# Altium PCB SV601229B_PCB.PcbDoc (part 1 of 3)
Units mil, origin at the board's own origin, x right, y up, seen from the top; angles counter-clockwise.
Board outline 3875 x 2375 mil, 10 copper layers (Top Layer, MidLayer1, MidLayer2, MidLayer3, MidLayer4, MidLayer5, MidLayer6, MidLayer7, MidLayer8, Bottom Layer), stack 98 mil thick; 184 components, 75 nets, 694 pads, 496 vias.
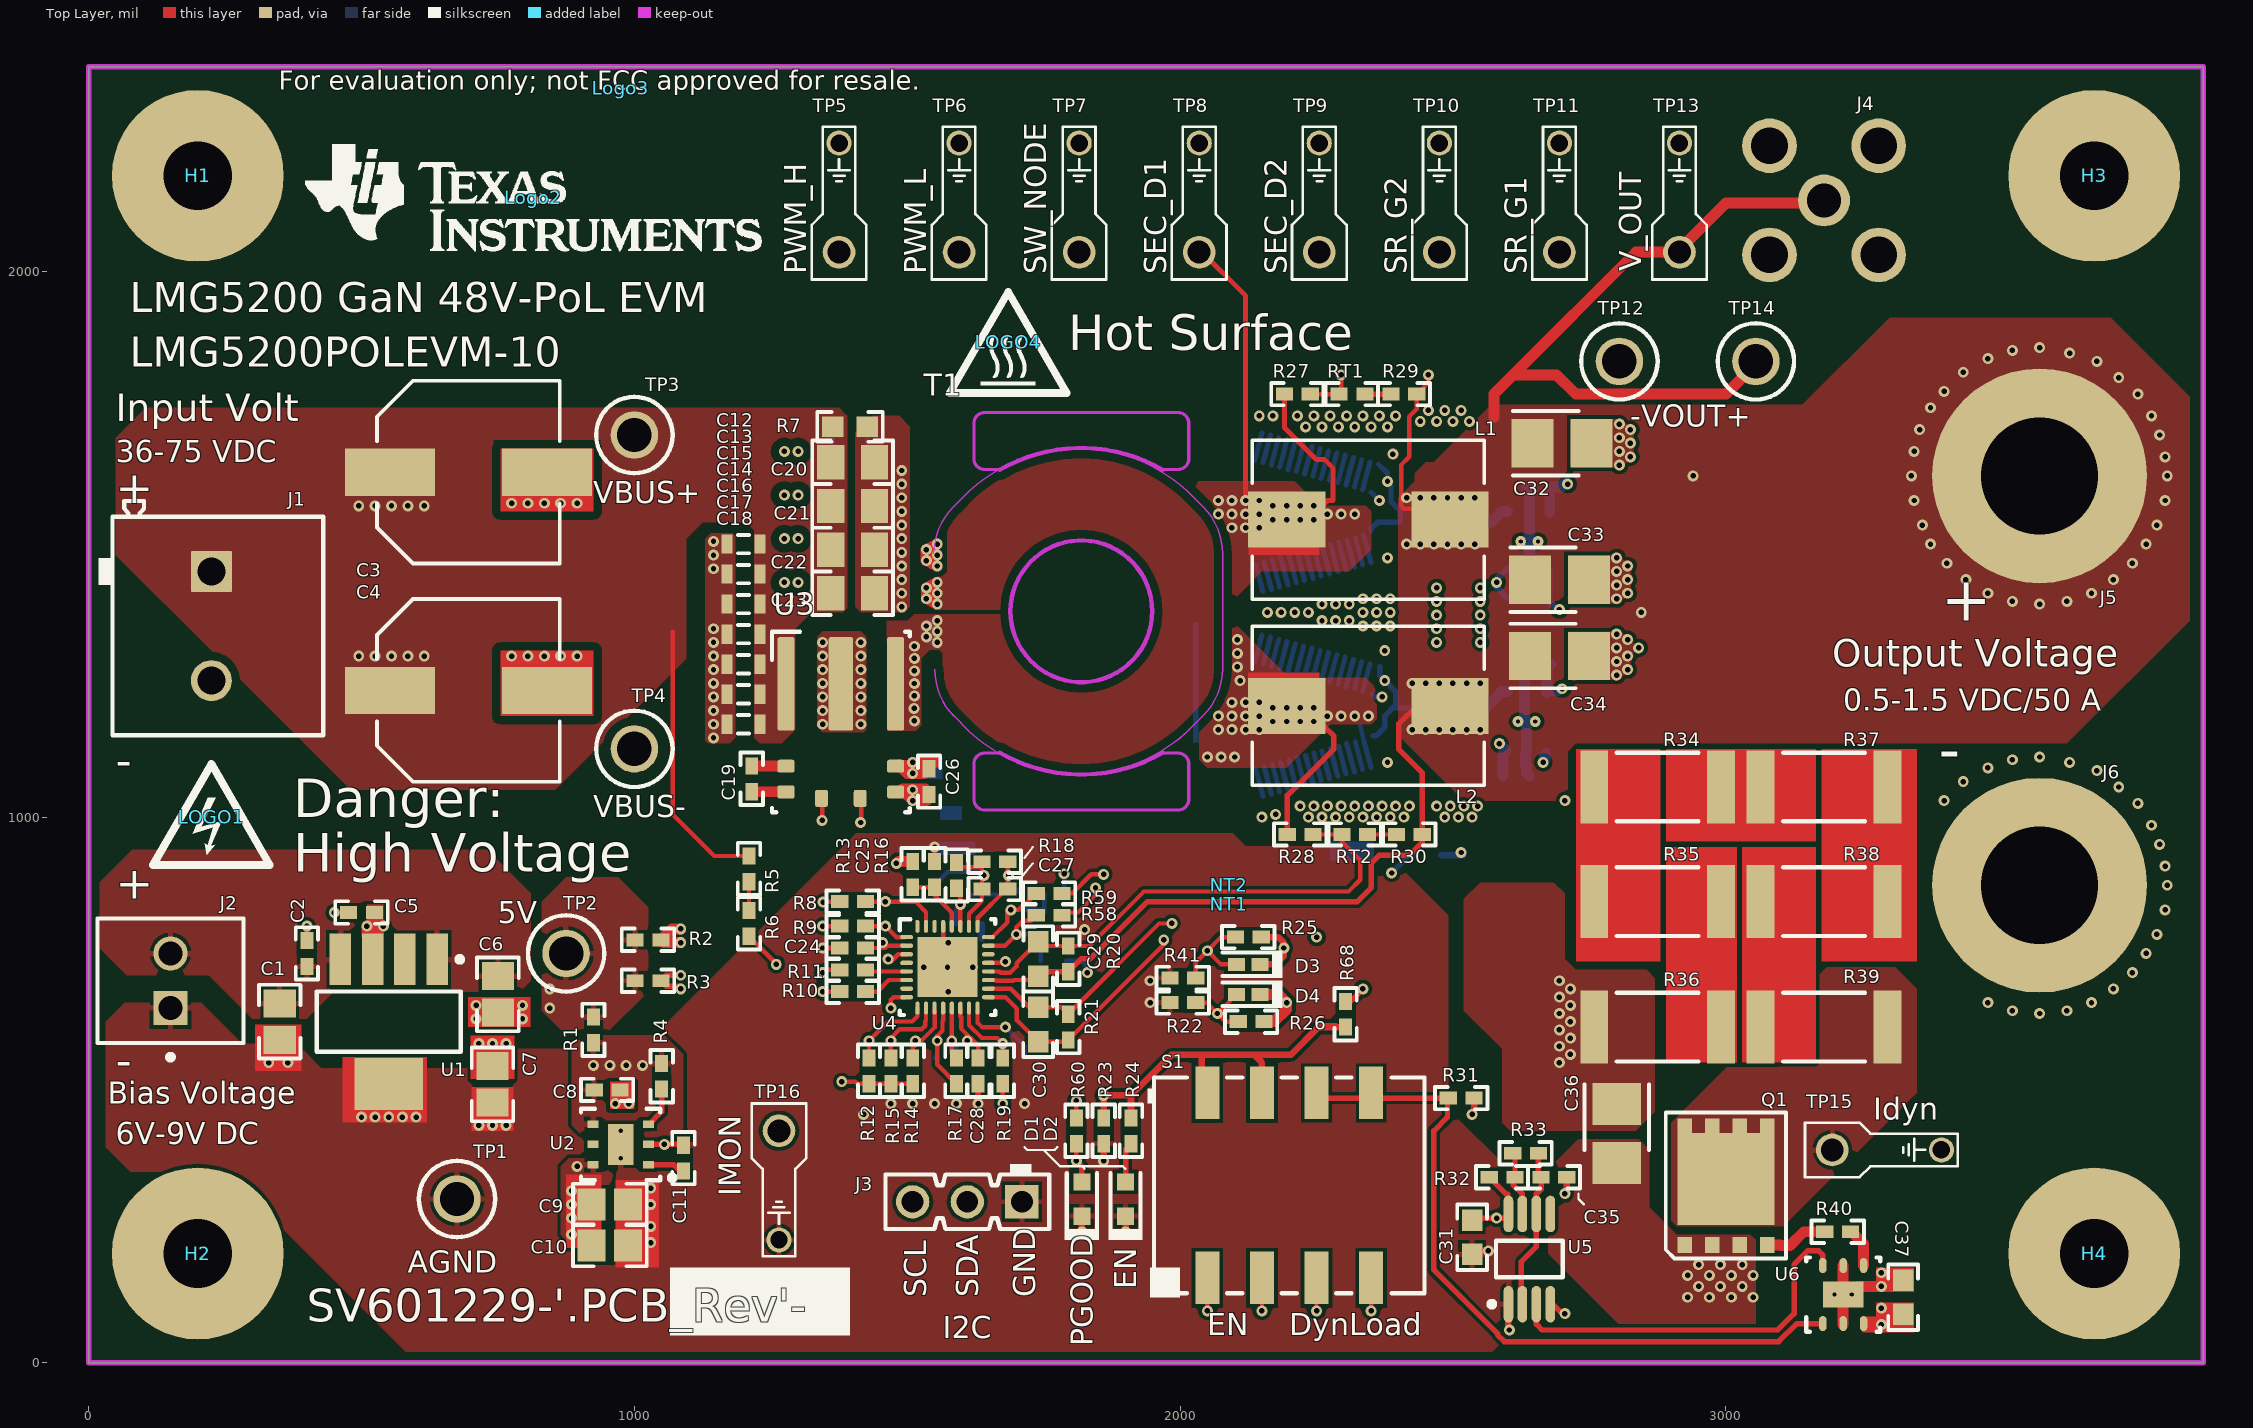
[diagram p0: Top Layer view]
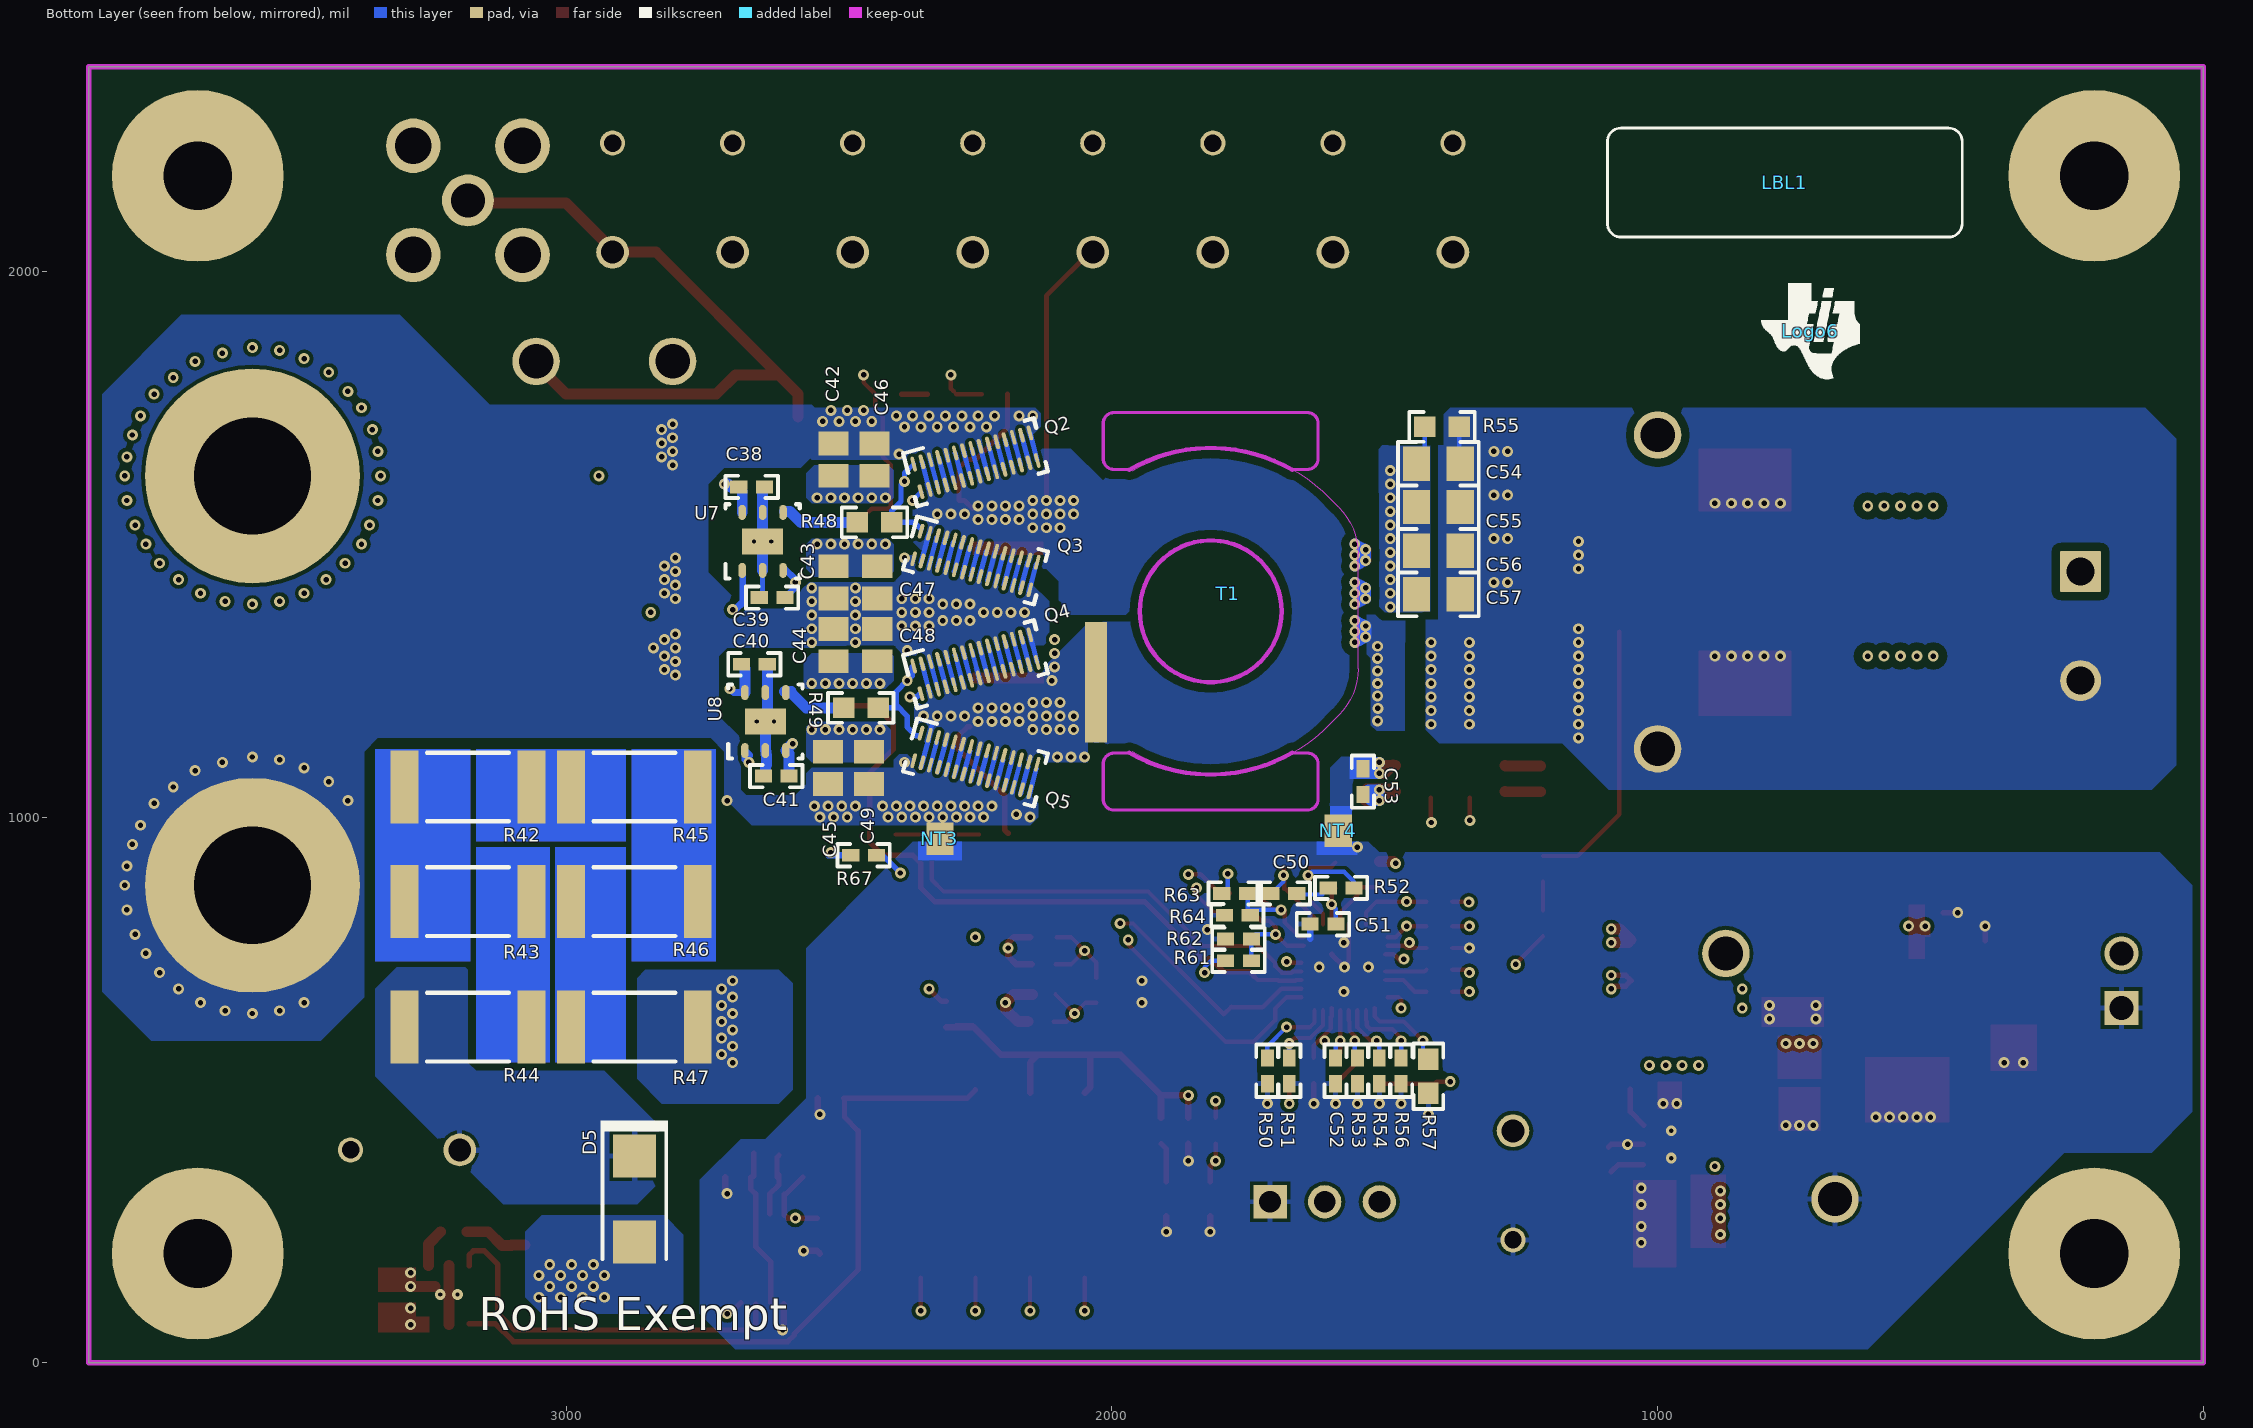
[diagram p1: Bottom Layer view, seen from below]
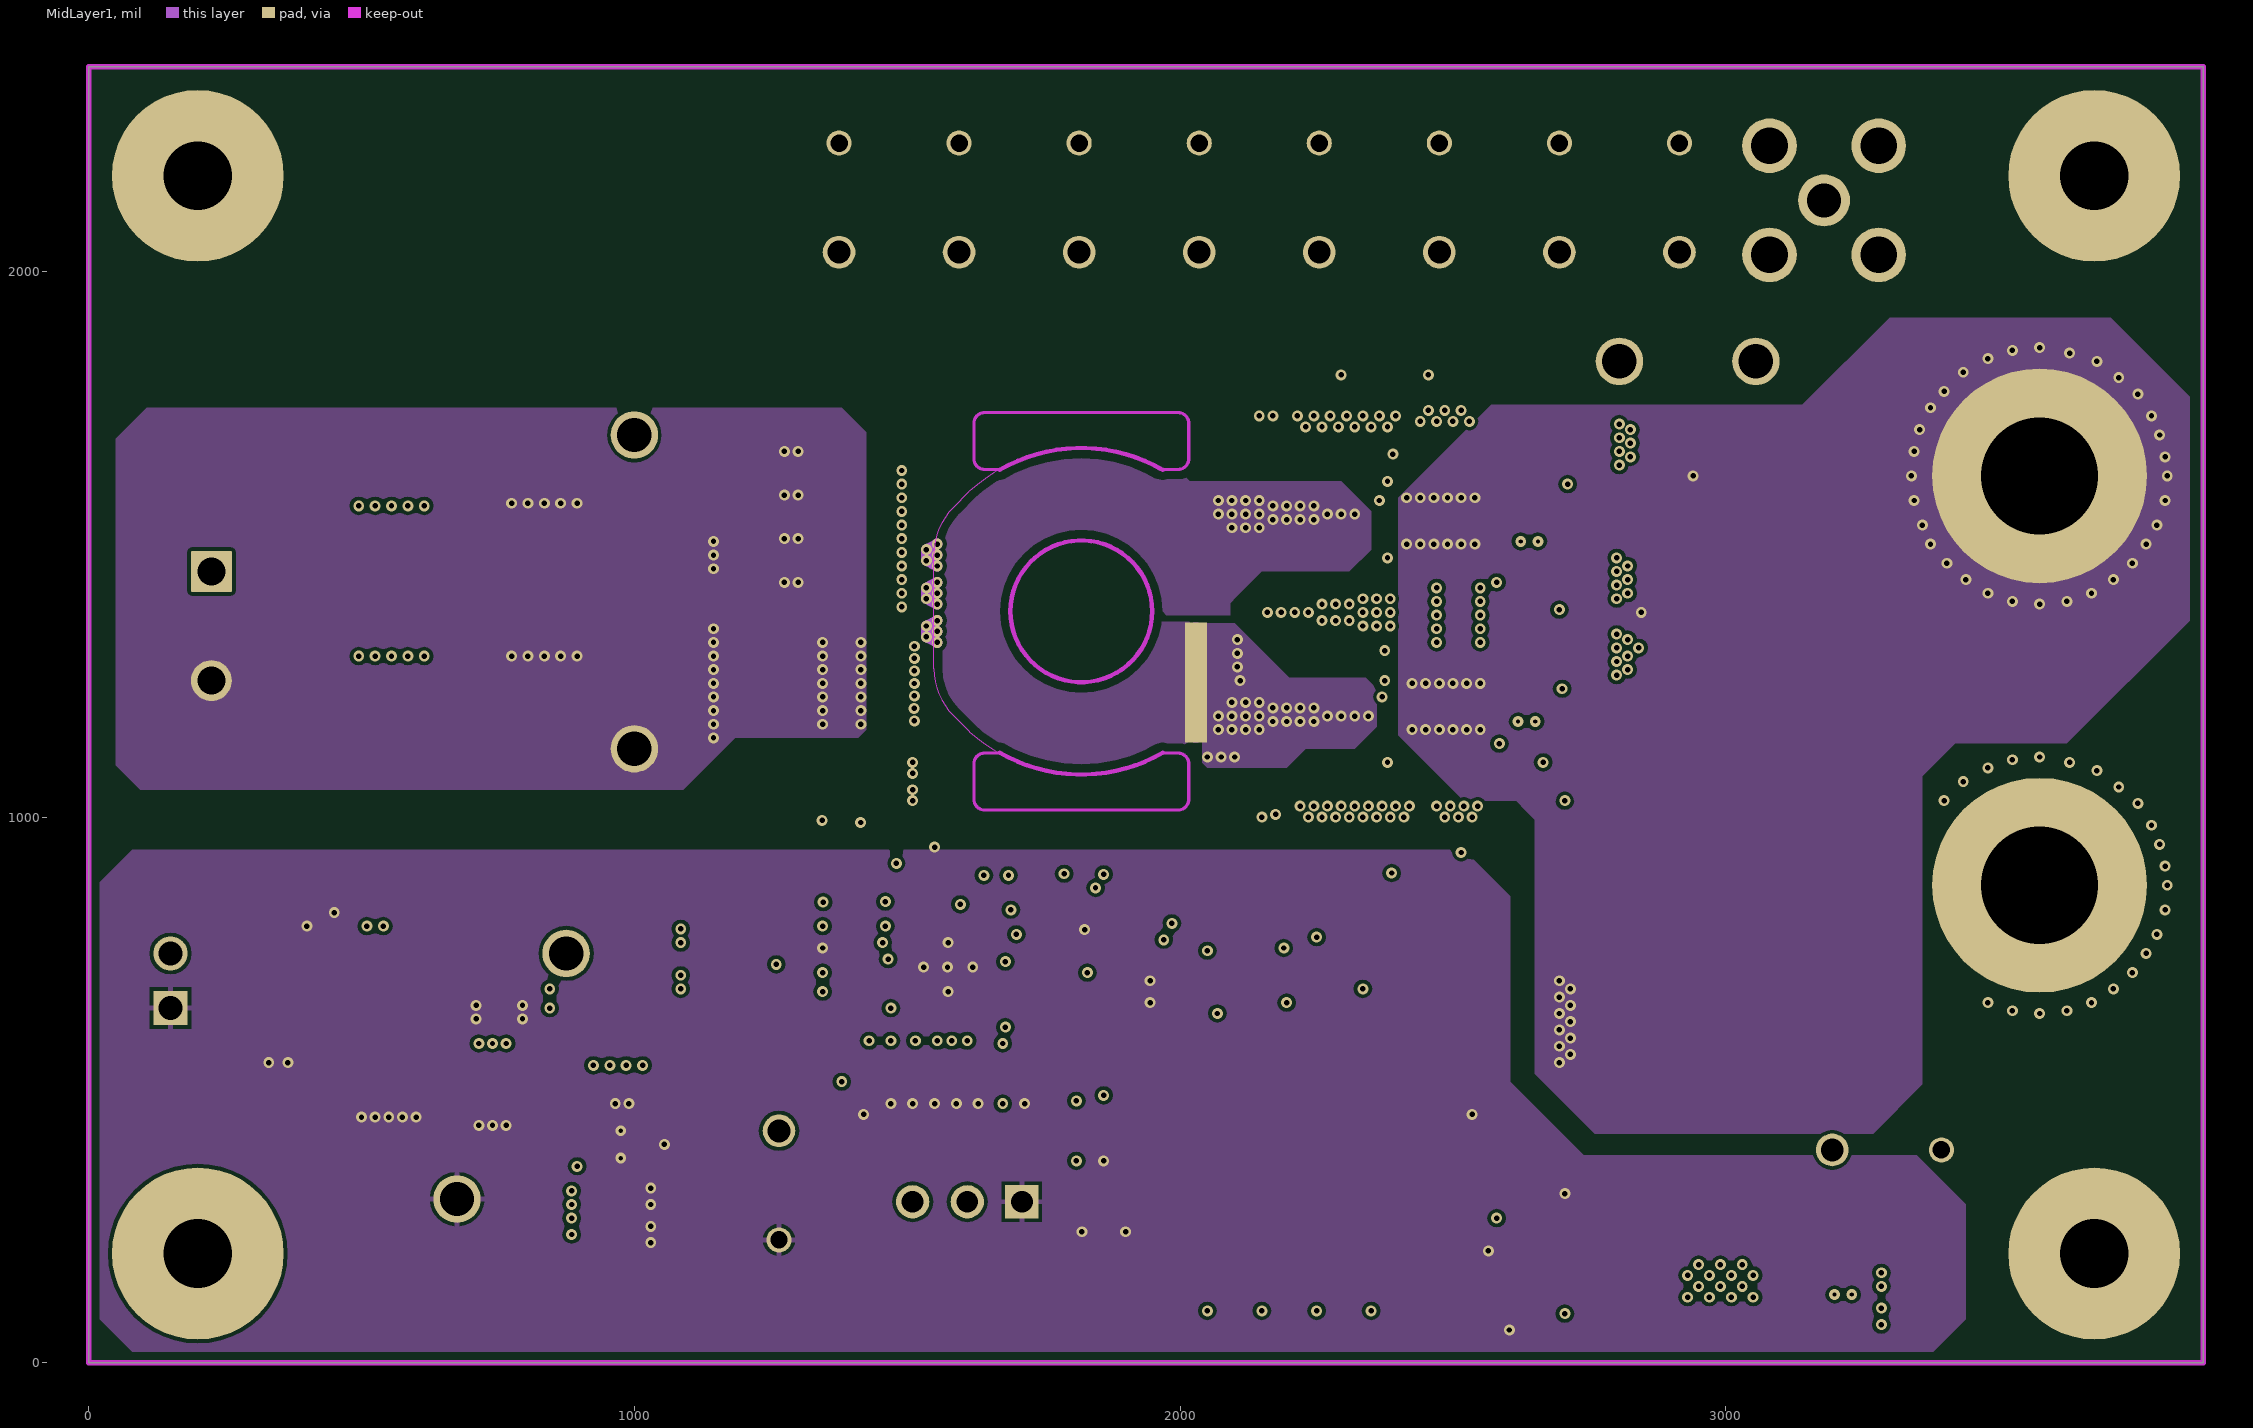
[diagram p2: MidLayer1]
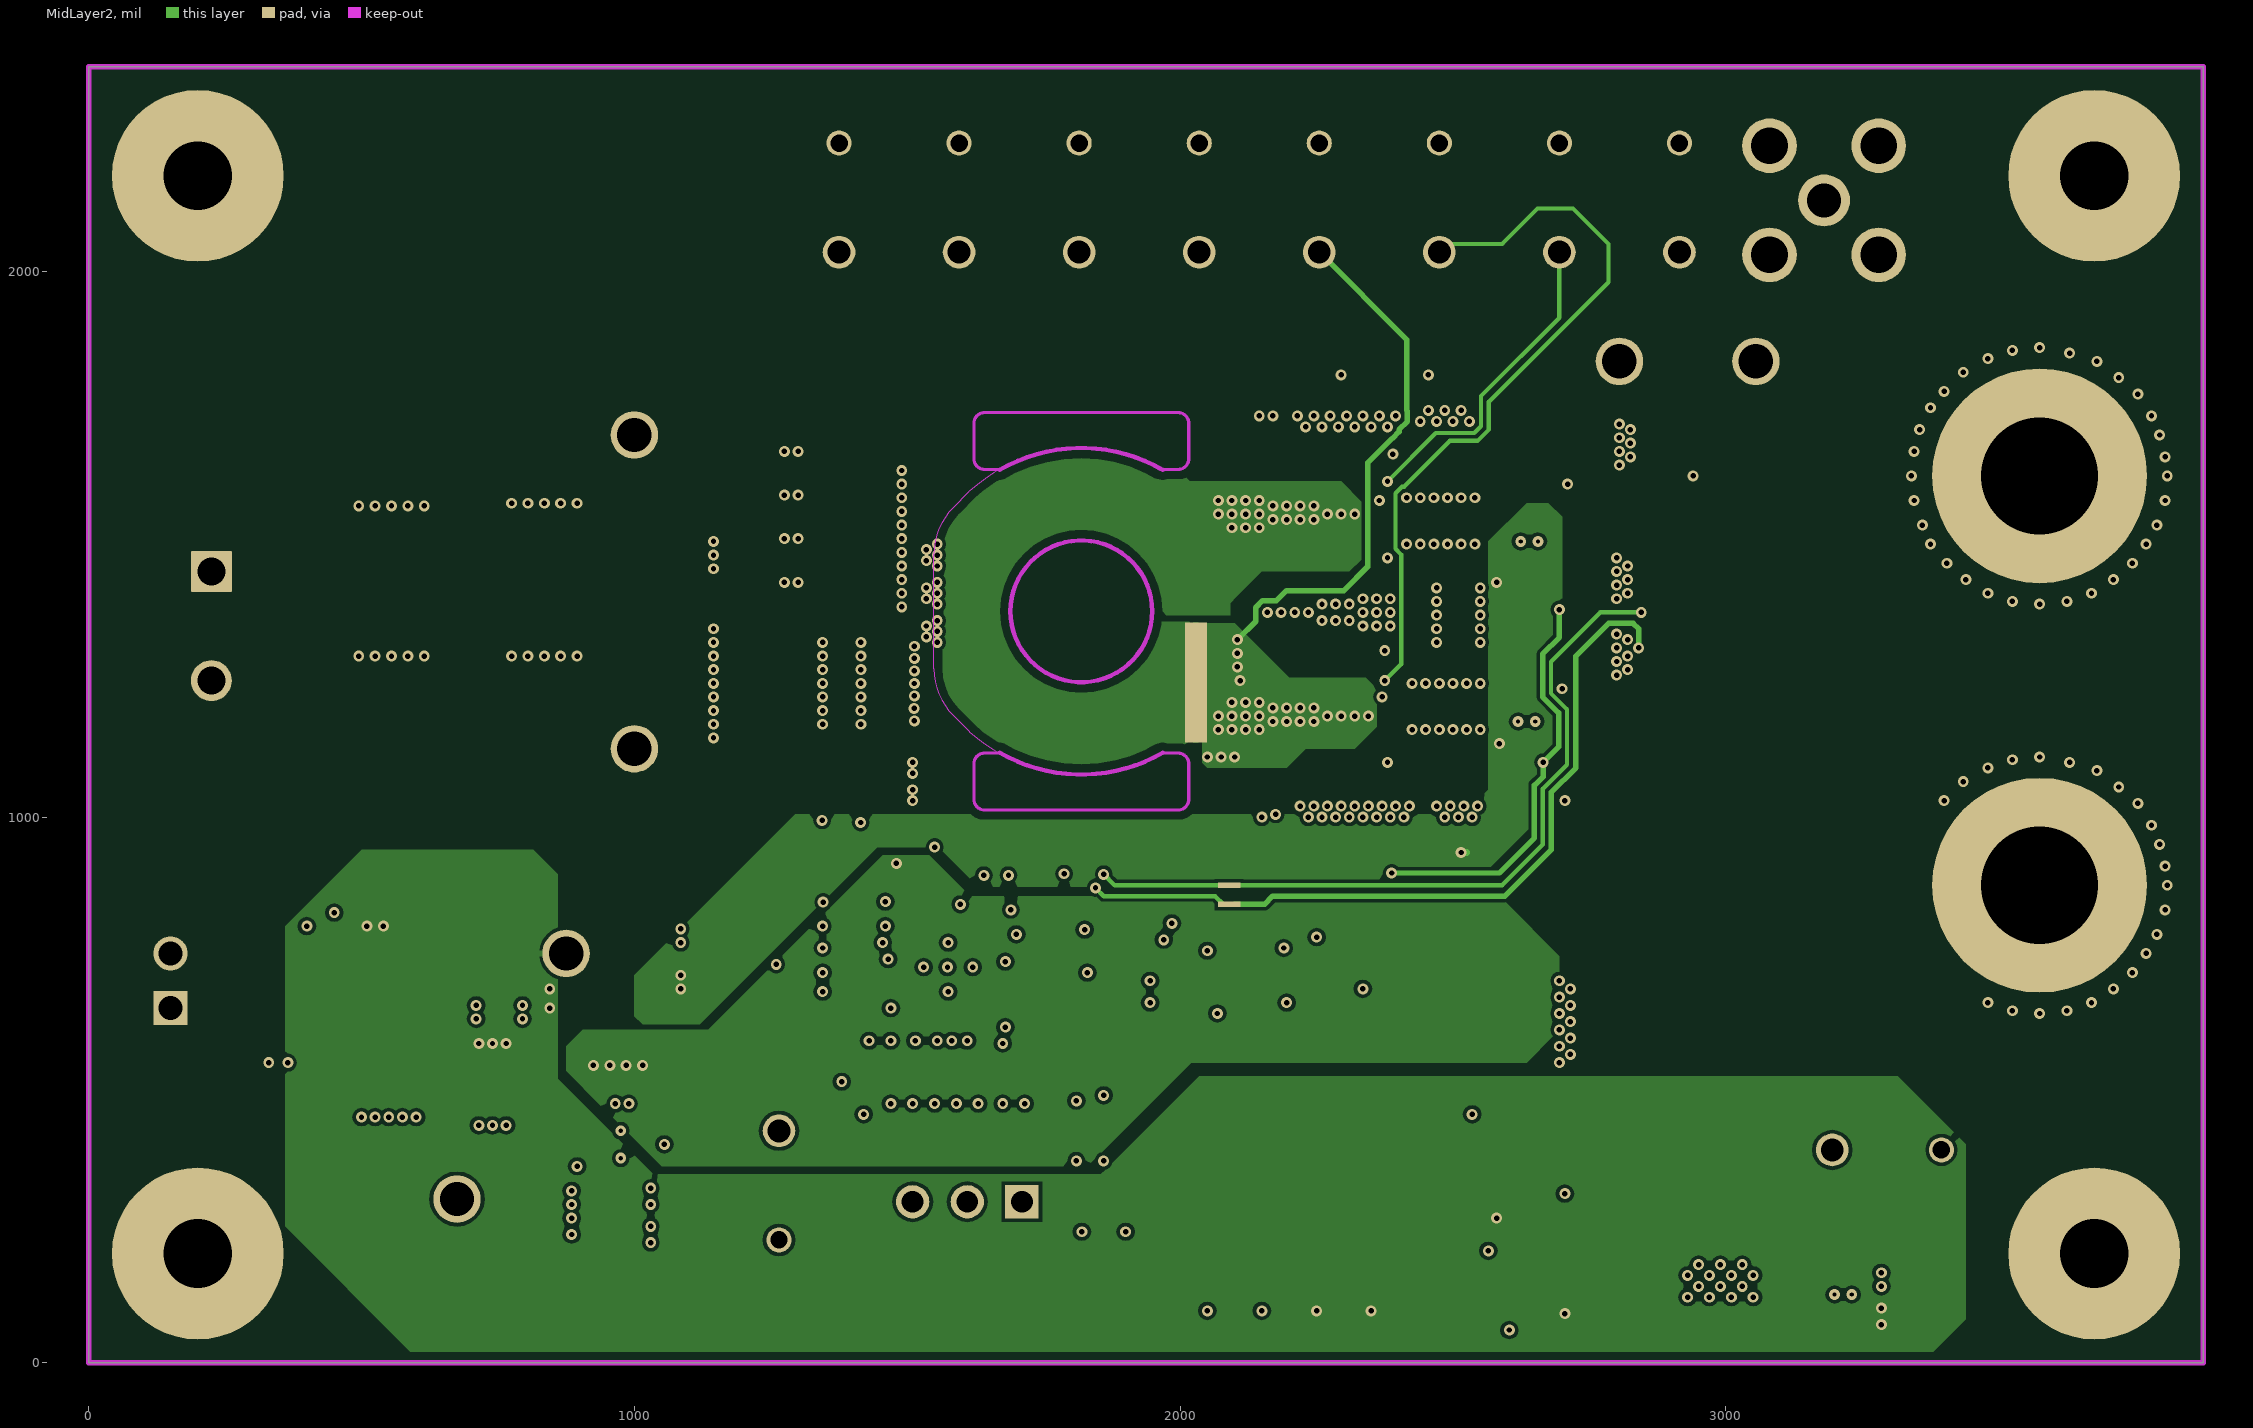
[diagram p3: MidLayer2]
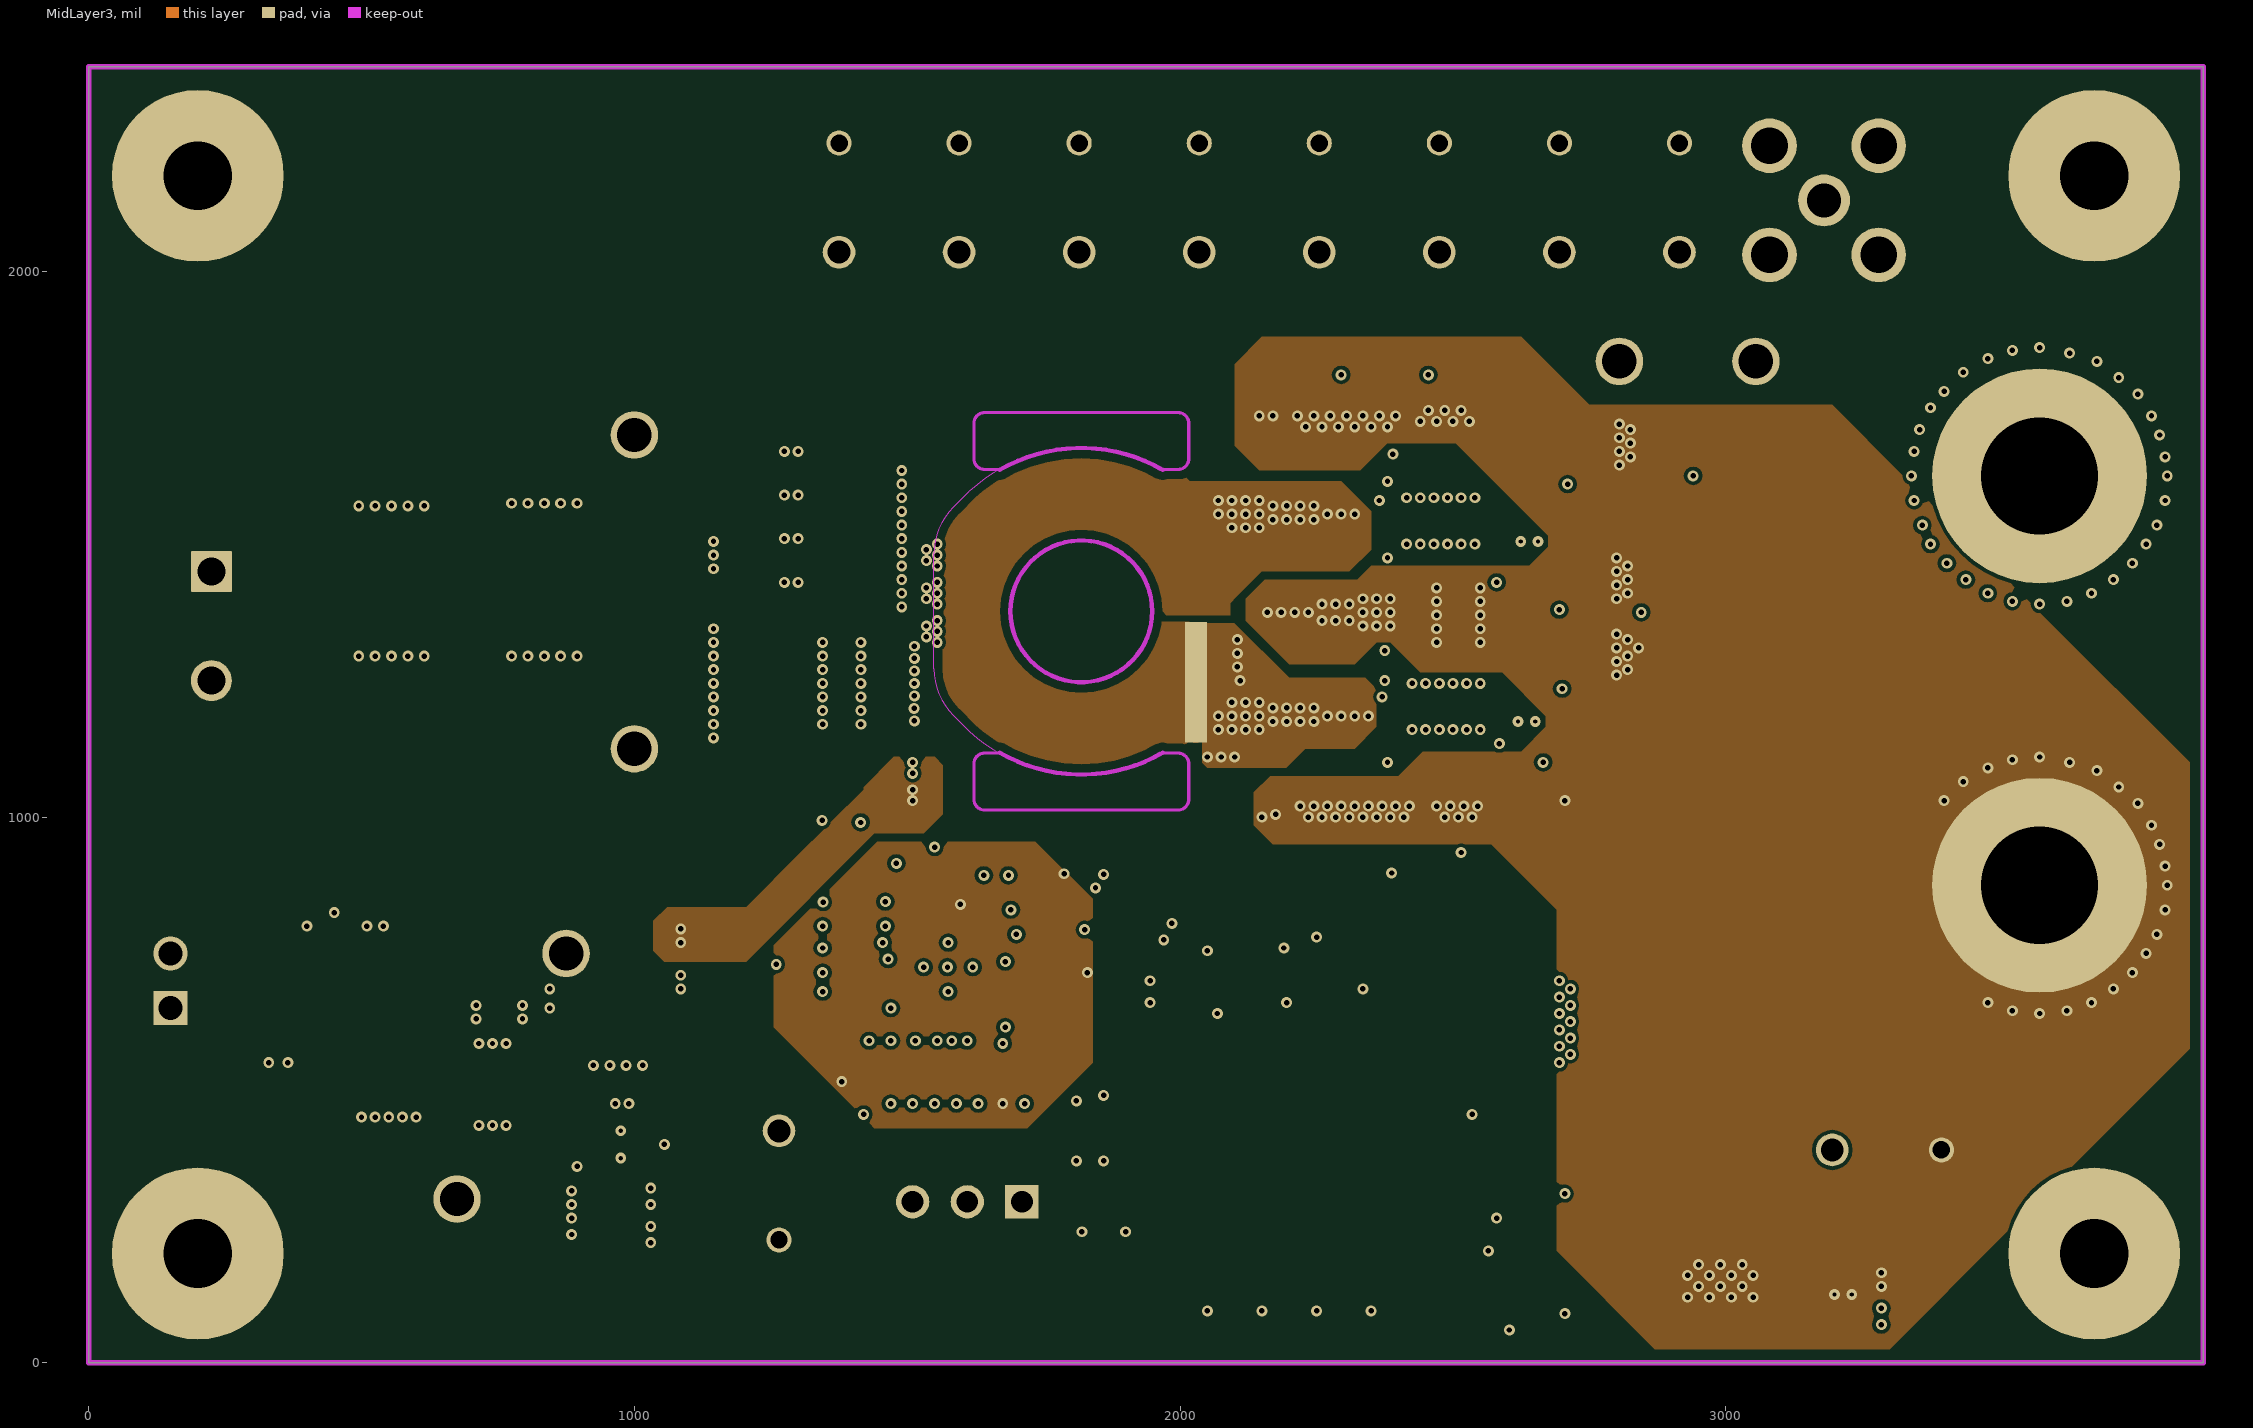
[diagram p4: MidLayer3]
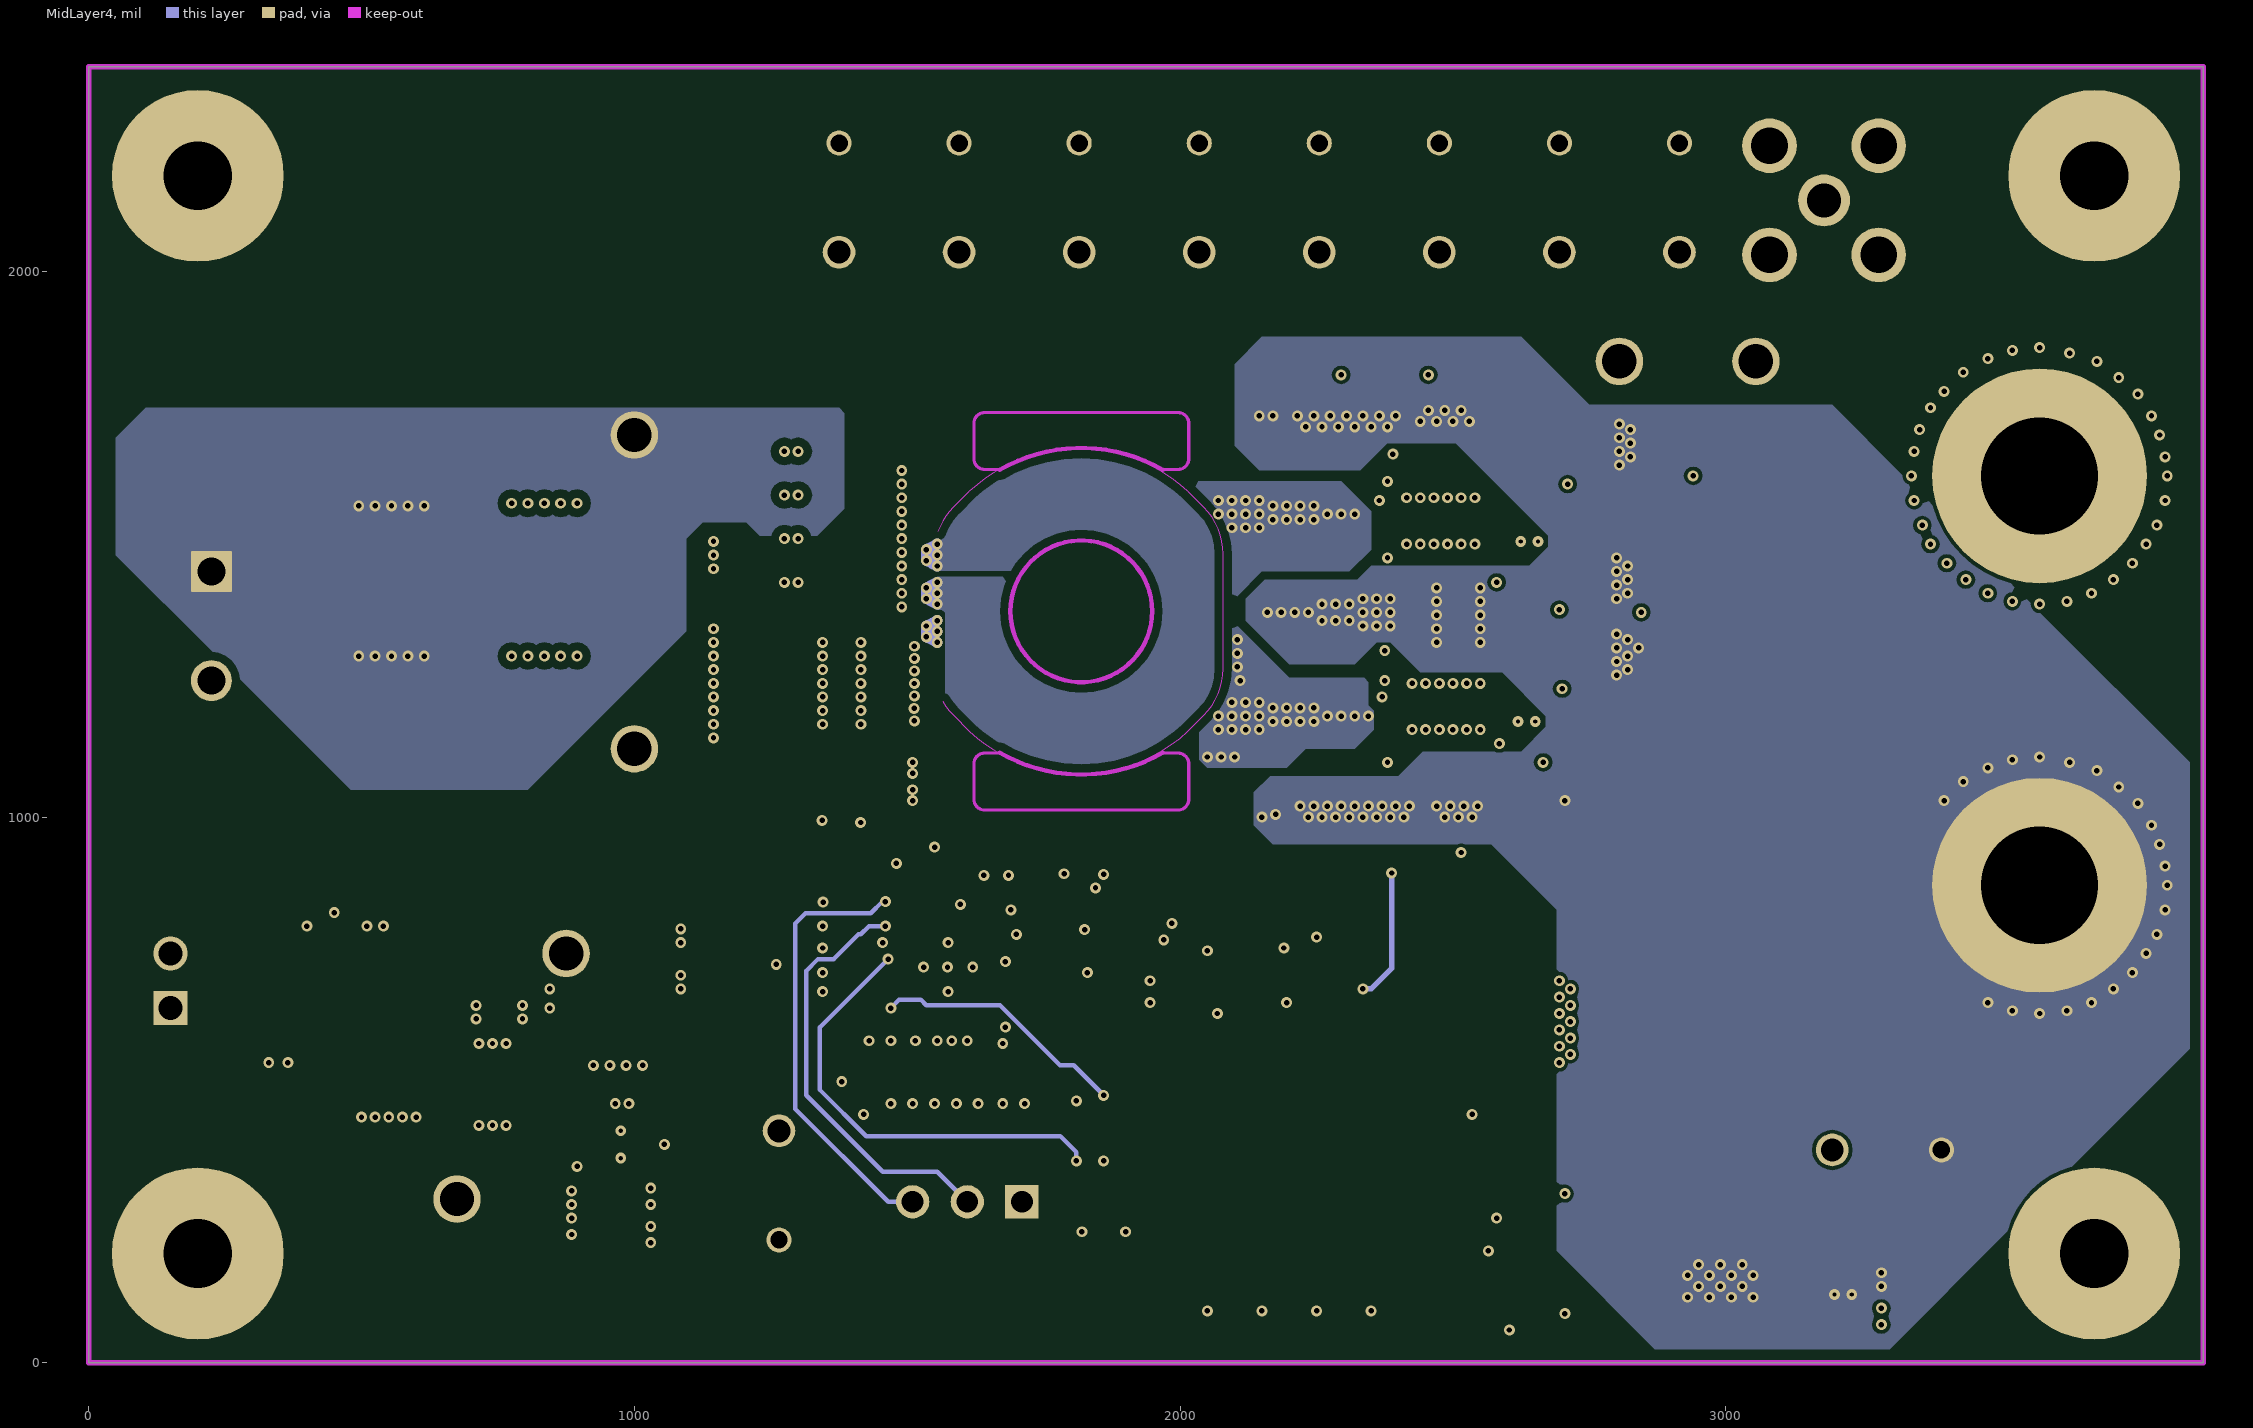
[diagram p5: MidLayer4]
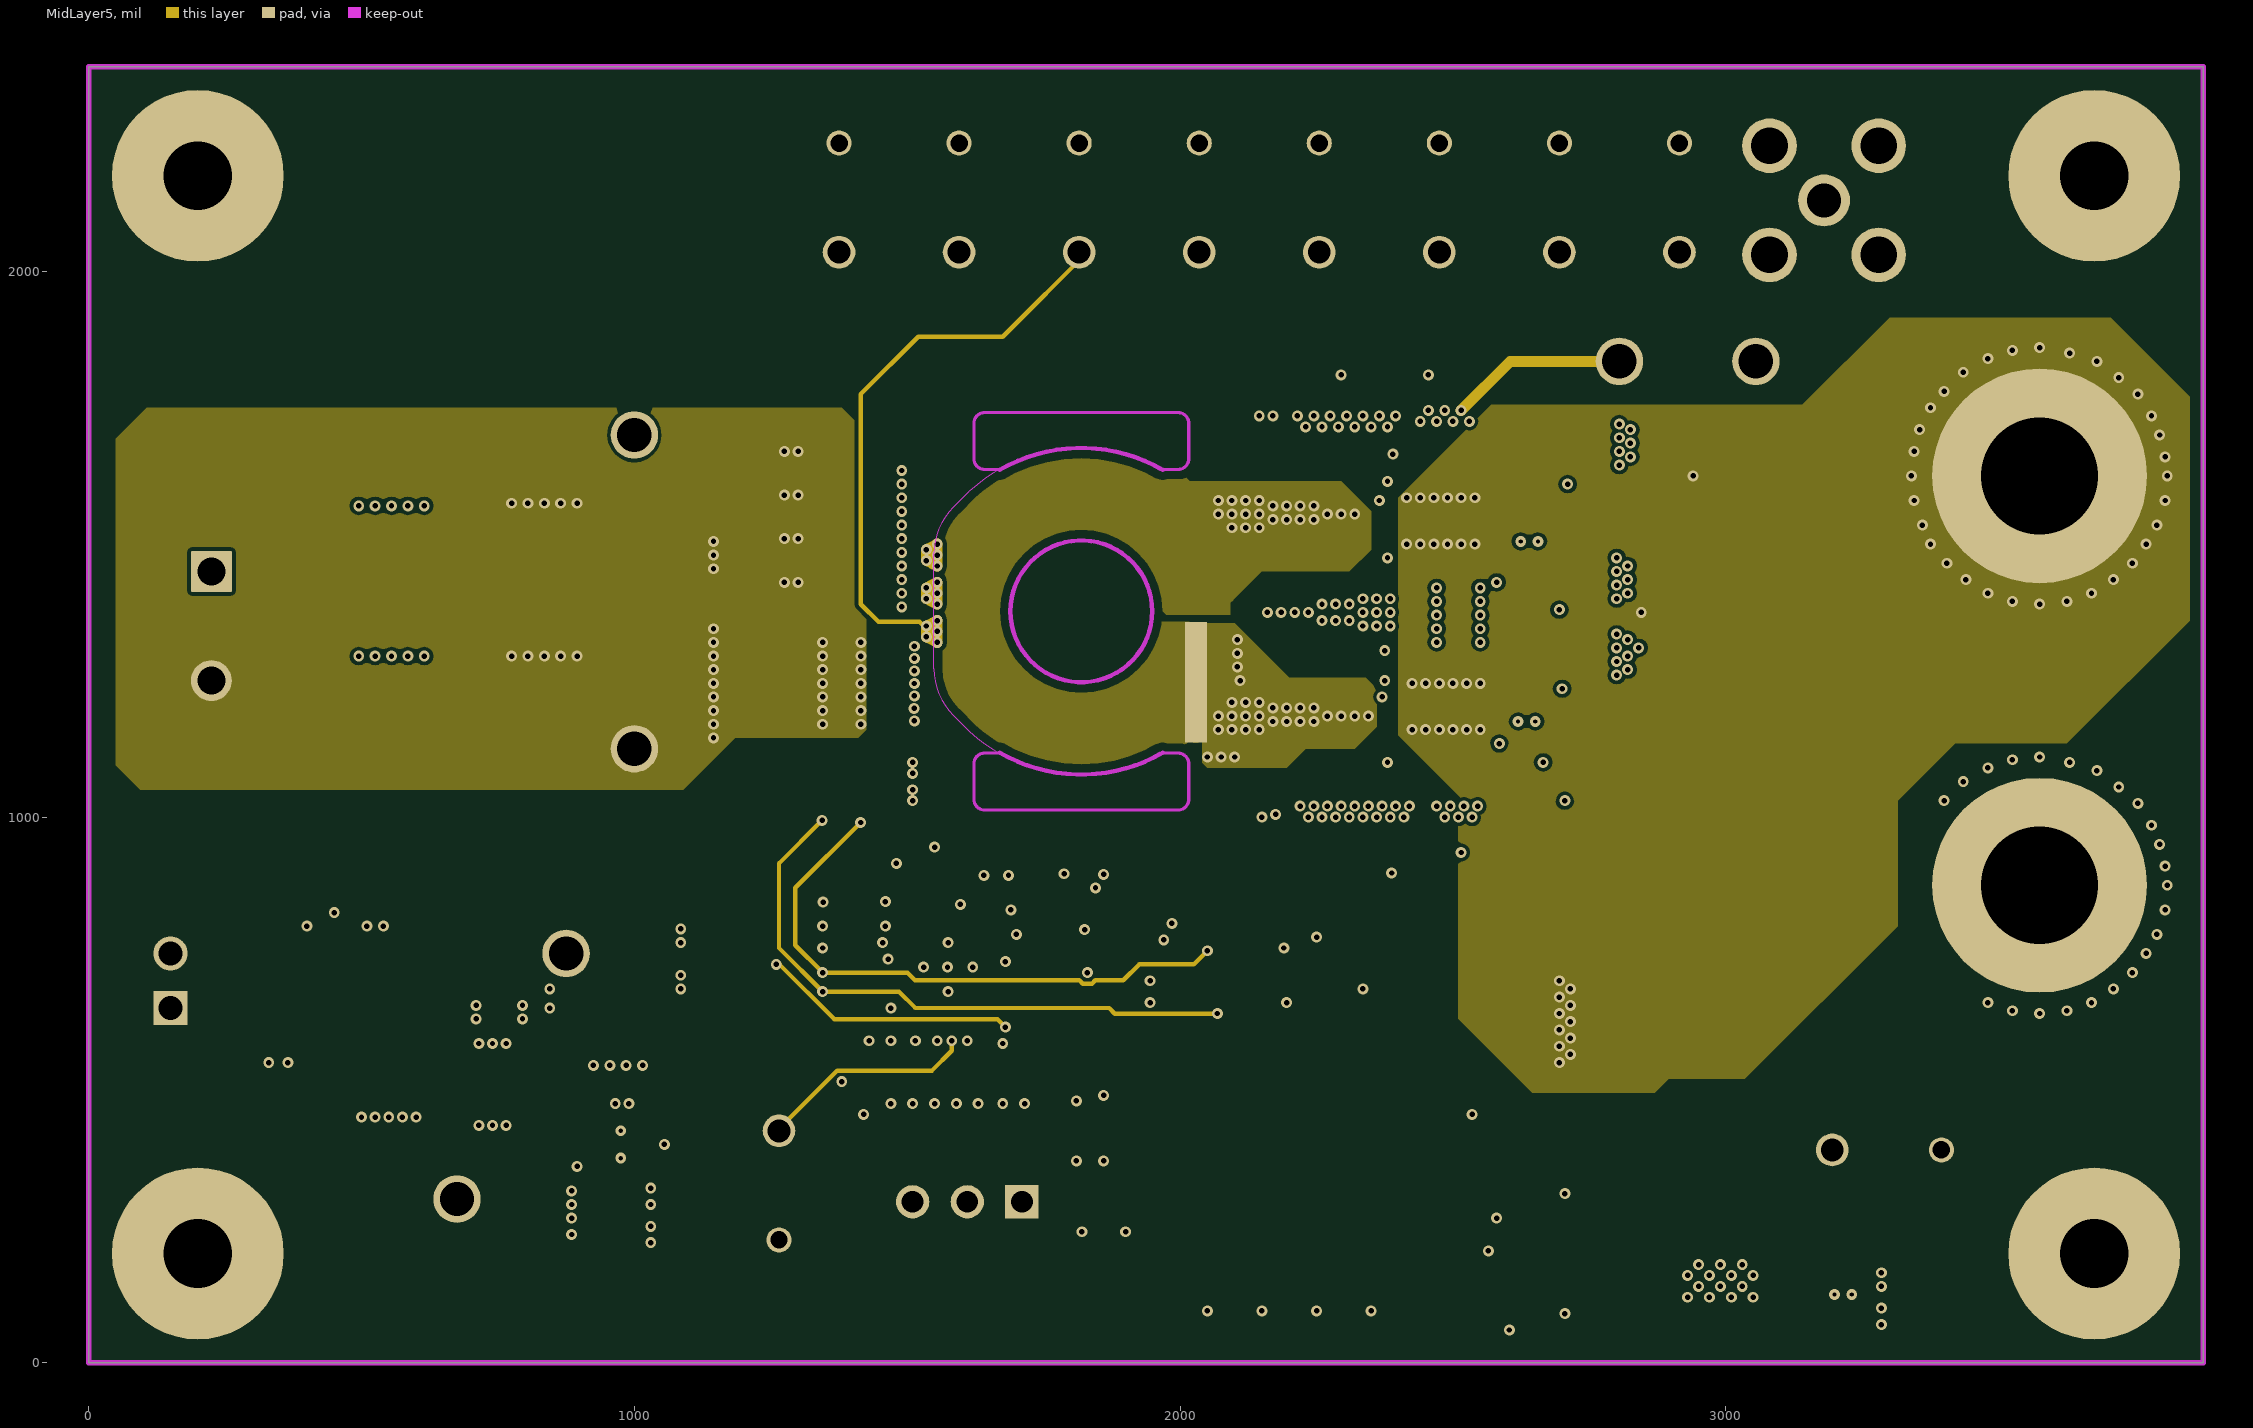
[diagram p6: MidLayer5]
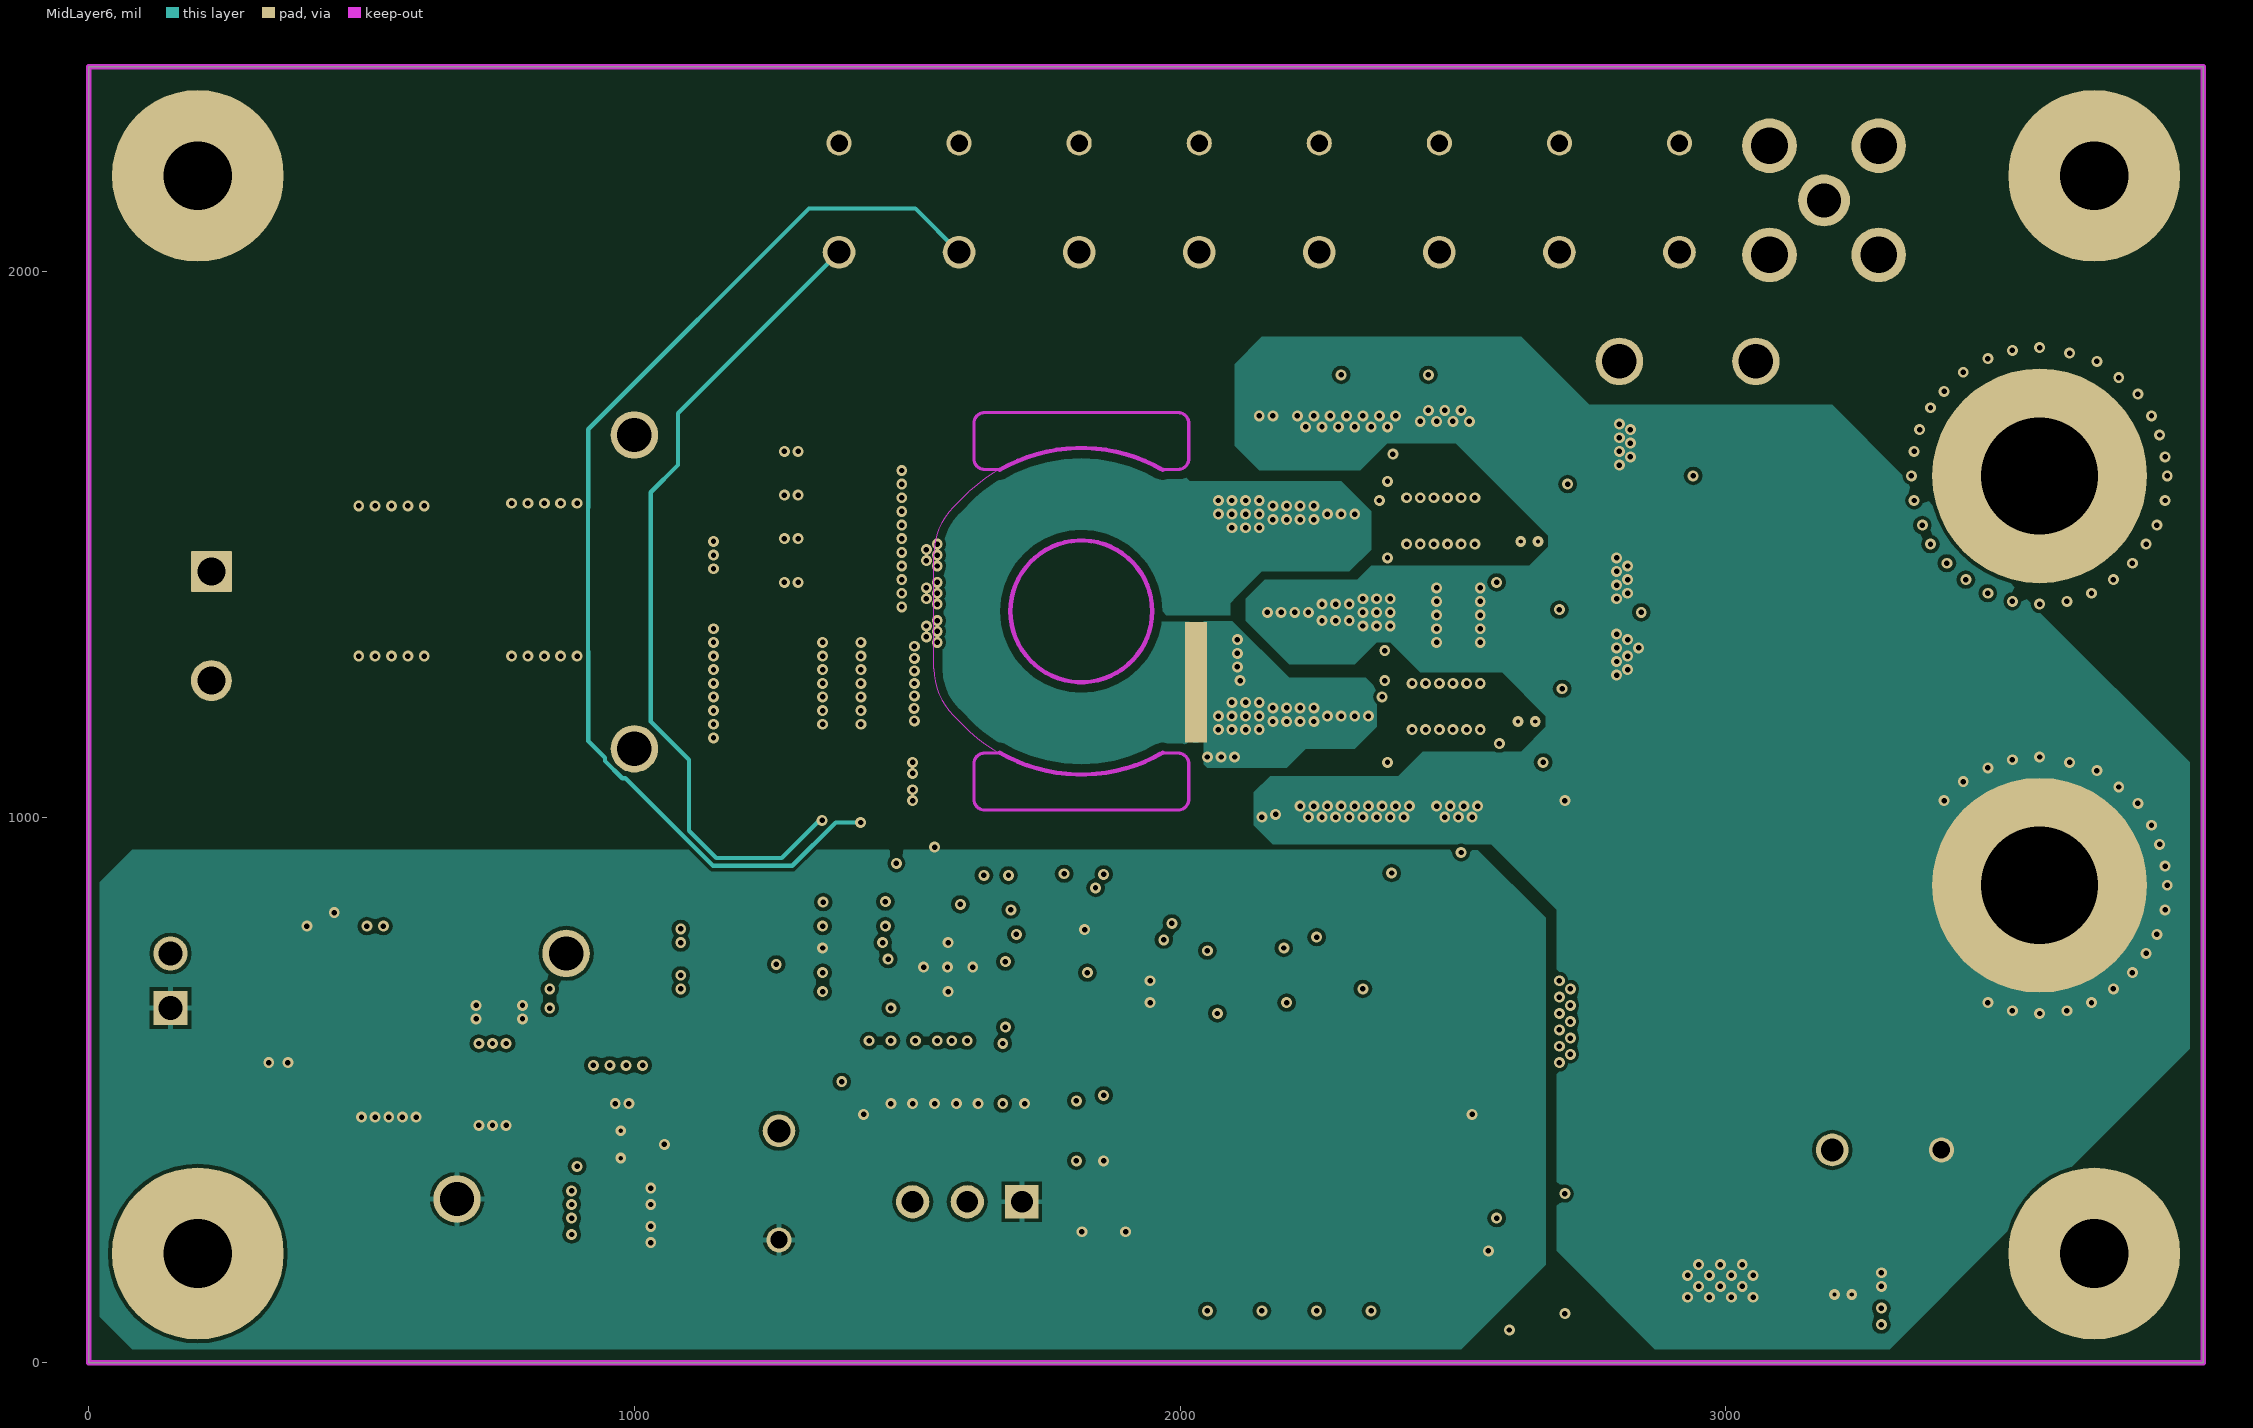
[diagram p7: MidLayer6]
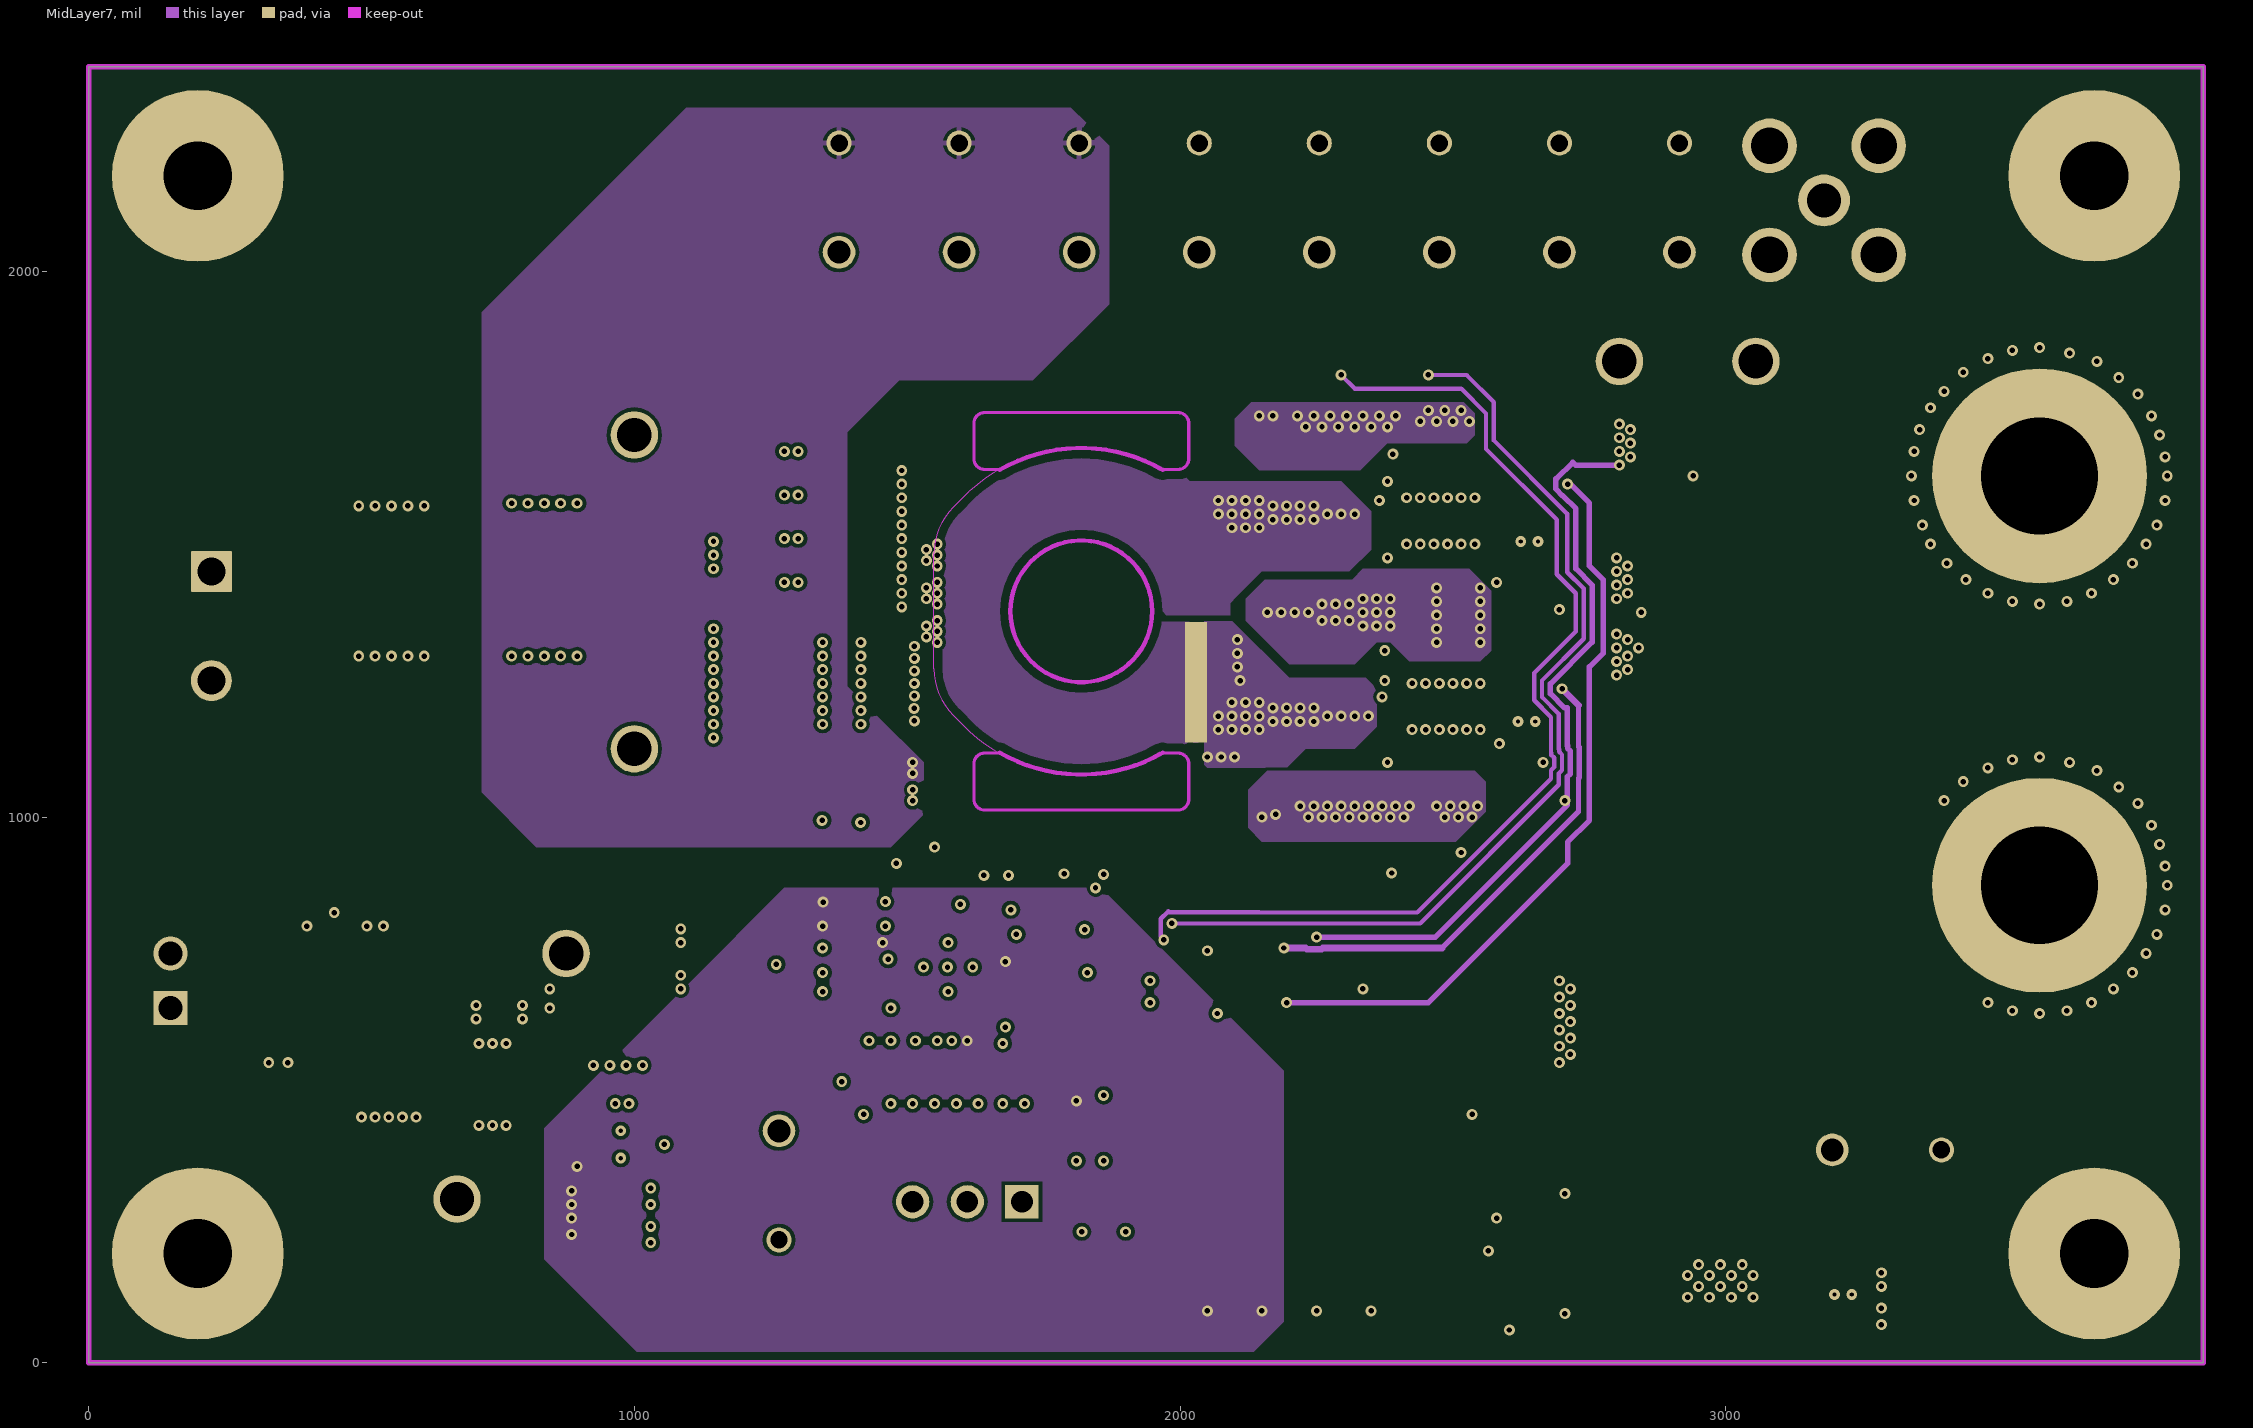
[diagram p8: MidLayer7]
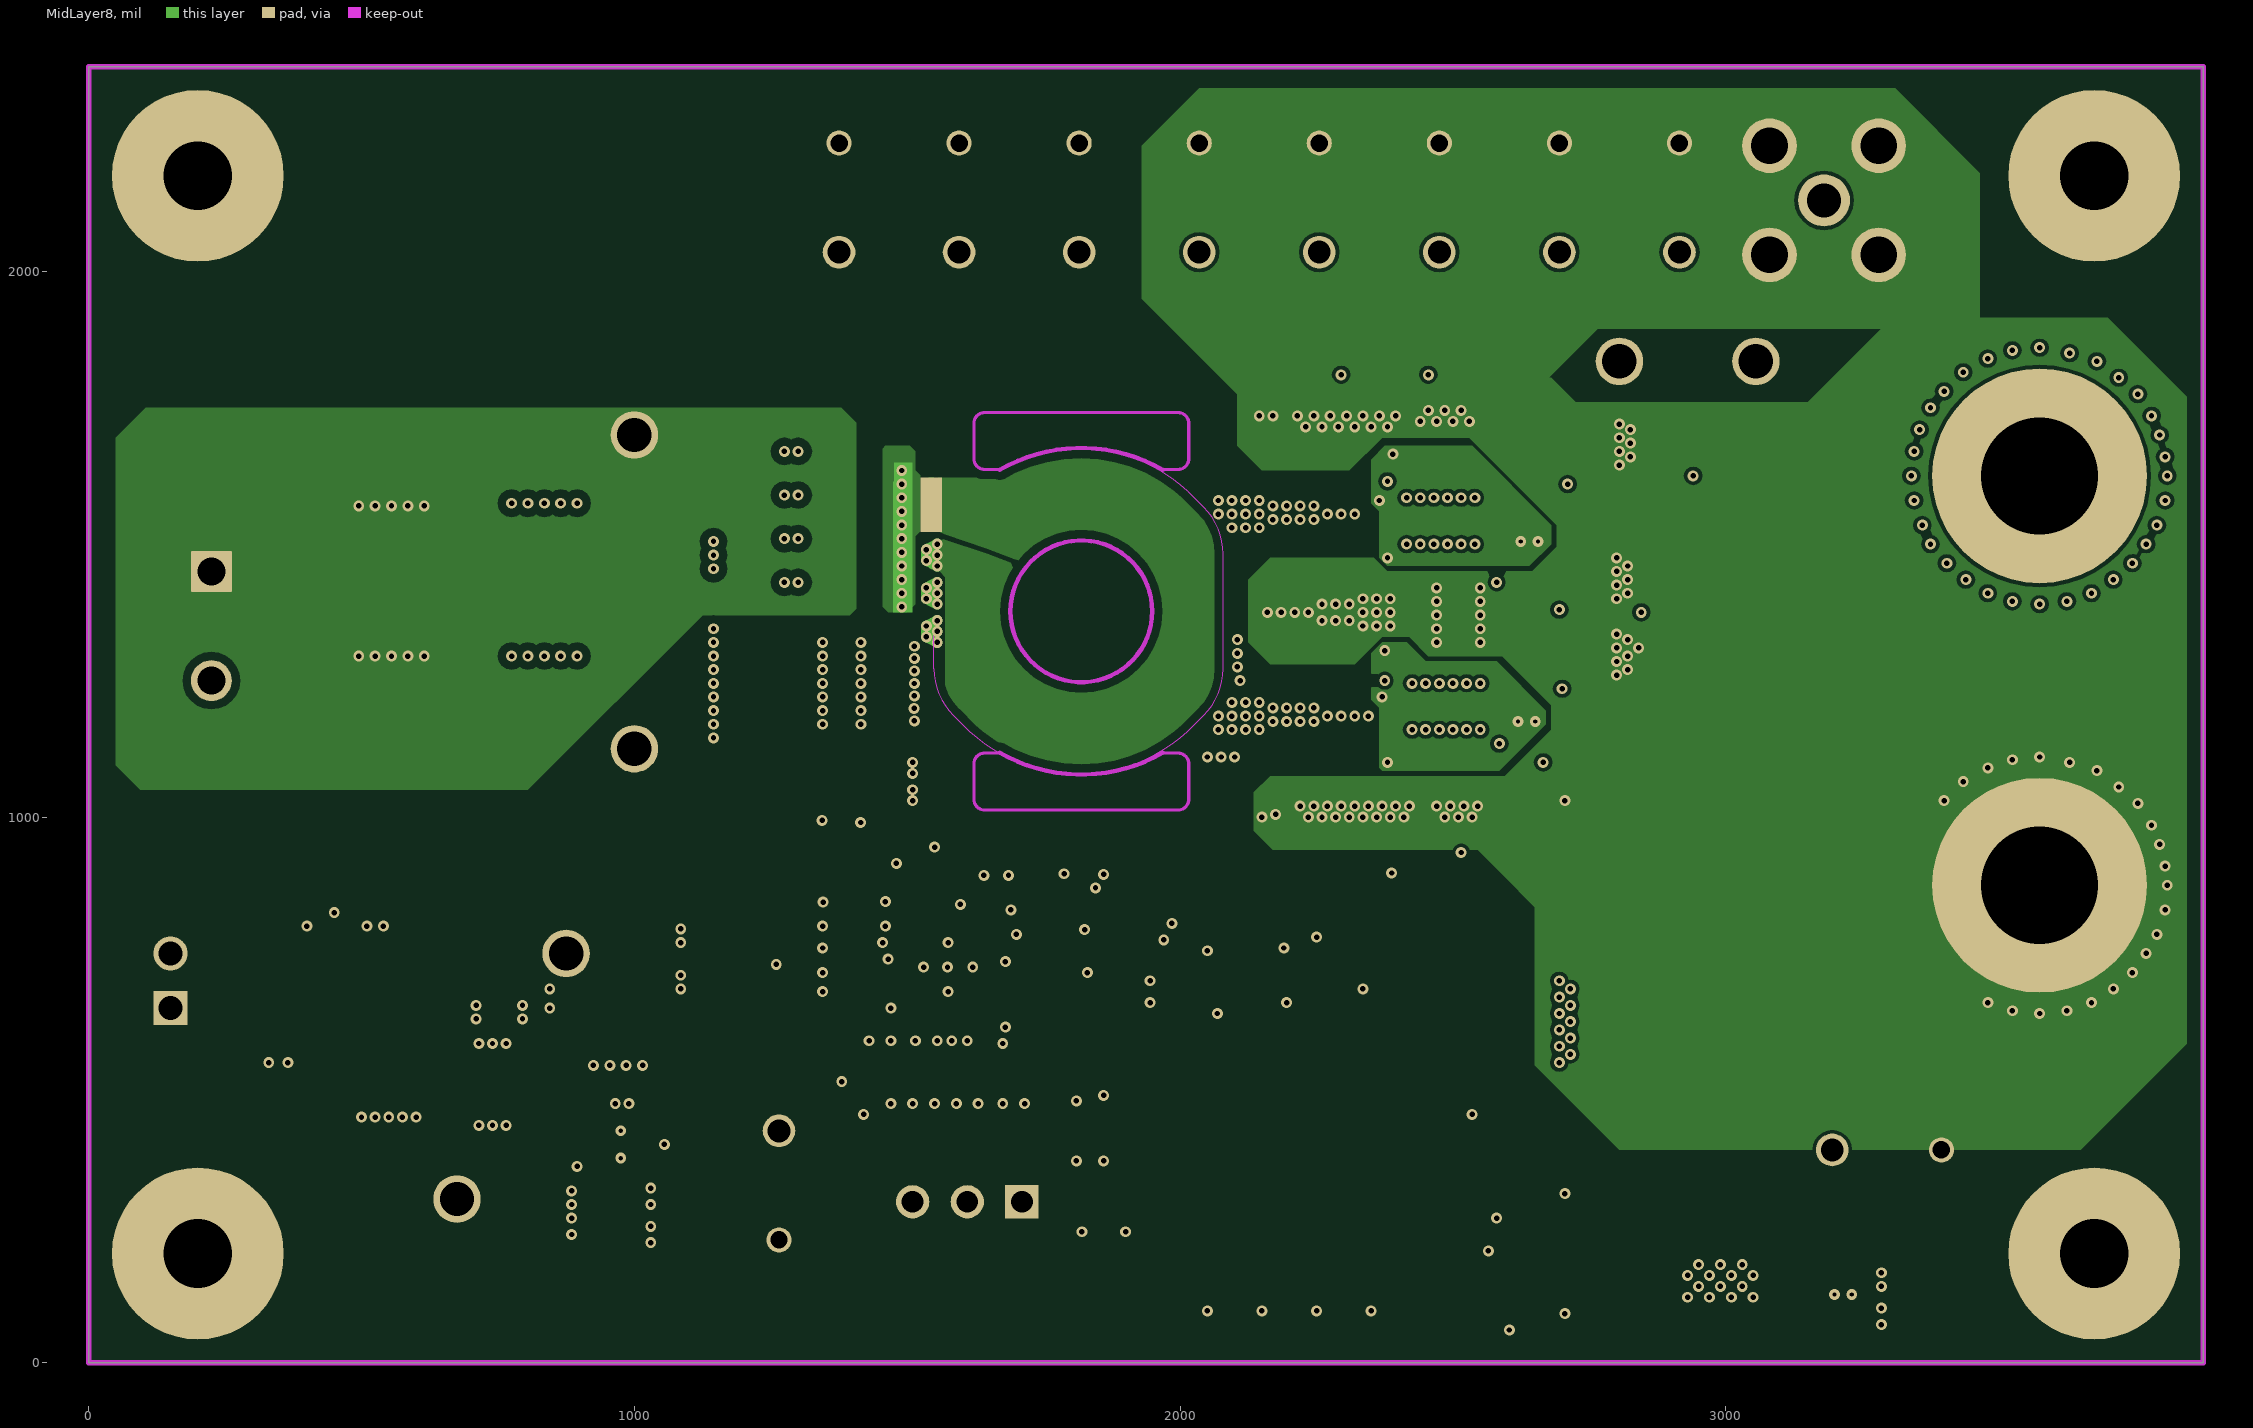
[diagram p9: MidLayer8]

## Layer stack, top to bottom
Top Solder: solder mask 0.4, Solder Resist, Dk 3.5
Top Layer: signal copper 2.8
Dielectric1: core 10, FR-4, Dk 4.8
MidLayer1: signal copper 2.8
Dielectric2: prepreg 5, FR-4, Dk 4.8
MidLayer2: signal copper 2.8
Dielectric3: core 10, FR-4, Dk 4.8
MidLayer3: signal copper 2.8
Dielectric4: prepreg 5, FR-4, Dk 4.8
MidLayer4: signal copper 2.8
Dielectric5: core 10, FR-4, Dk 4.8
MidLayer5: signal copper 2.8
Dielectric6: prepreg 5, FR-4, Dk 4.8
MidLayer6: signal copper 2.8
Dielectric7: core 10, FR-4, Dk 4.8
MidLayer7: signal copper 2.8
Dielectric8: prepreg 5, FR-4, Dk 4.8
MidLayer8: signal copper 2.8
Dielectric9: core 10, FR-4, Dk 4.8
Bottom Layer: signal copper 2.8
Bottom Solder: solder mask 0.4, Solder Resist, Dk 3.5

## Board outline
0,0 0,2375 3875,2375 3875,0

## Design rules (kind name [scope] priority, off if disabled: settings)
AcuteAngle [All] p1 off: minimum=4.50000000000000E+0001 checktracksonly=TRUE
AssemblyTestPointUsage [All] p1: valid=2
Clearance Clearance_Keepout [OnCopper and Not IsKeepout vs IsKeepOut] p1: gap=14.9 ignorepadtopadclearanceinfootprint=FALSE except(0: Arc-Hole Track-Hole SMDPad-Hole THPad-Hole Via-Hole Fill-Hole Poly-Hole Region-Hole Text-Hole)
Clearance Clearance_BoardEdge_MountingHoles [OnCopper and InComponentClass('Mounting Holes') vs IsKeepOut] p2: gap=30 ignorepadtopadclearanceinfootprint=FALSE except(0: Arc-Hole Track-Hole SMDPad-Hole THPad-Hole Via-Hole Fill-Hole Poly-Hole Region-Hole Text-Hole)
Clearance Clearance_BoardEdge_Poly [OnCopper and InPoly vs IsKeepOut] p3: gap=25 ignorepadtopadclearanceinfootprint=FALSE except(0: Arc-Hole Track-Hole SMDPad-Hole THPad-Hole Via-Hole Fill-Hole Poly-Hole Region-Hole Text-Hole)
Clearance Clearance_BoardEdge [OnCopper and Not InComponentClass('Logo') and not InComponentClass('FiducialMark') and not InRegion(1000,500,4000,800) and Not IsKeepout vs OnLayer('M1 Board Outline')] p4: gap=40 ignorepadtopadclearanceinfootprint=FALSE except(0: Arc-Hole Track-Hole SMDPad-Hole THPad-Hole Via-Hole Fill-Hole Poly-Hole Region-Hole Text-Hole)
Clearance Clearance_HV2_MID [InNetClass('HV2') and OnMid] p5: gap=8 ignorepadtopadclearanceinfootprint=FALSE except(0: Arc-Hole Track-Hole SMDPad-Hole THPad-Hole Via-Hole Fill-Hole Poly-Hole Region-Hole Text-Hole)
Clearance Clearance_HV [(InNetClass('HV2') or InNetClass('HV1')) and not InComponentClass('HV_NoErr') vs not OnMid] p6: gap=15 ignorepadtopadclearanceinfootprint=FALSE except(0: Arc-Hole Track-Hole SMDPad-Hole THPad-Hole Via-Hole Fill-Hole Poly-Hole Region-Hole Text-Hole)
Clearance Clearance_Poly [InPolygon] p7: gap=6.5 ignorepadtopadclearanceinfootprint=FALSE except(0: Arc-Hole Track-Hole SMDPad-Hole THPad-Hole Via-Hole Fill-Hole Poly-Hole Region-Hole Text-Hole)
Clearance [Not IsKeepOut vs Not IsKeepOut] p8: gap=6.4 ignorepadtopadclearanceinfootprint=FALSE except(0: Arc-Hole Track-Hole SMDPad-Hole THPad-Hole Via-Hole Fill-Hole Poly-Hole Region-Hole Text-Hole)
Clearance Clearance_Keepout_orig [OnCopper and Not InComponentClass('Logo') and not InComponentClass('FiducialMark') and Not IsKeepout and Not (InNetClass('PPRI') and isVia) vs IsKeepOut] p9: gap=14.9 ignorepadtopadclearanceinfootprint=FALSE except(0: Arc-Hole Track-Hole SMDPad-Hole THPad-Hole Via-Hole Fill-Hole Poly-Hole Region-Hole Text-Hole)
ComponentClearance ComponentClearance_Shunt [InComponentClass('Header') vs InComponentClass('Shunt')] p1: gap=0 collisioncheckmode=3 verticalgap=0 showdistances=FALSE
ComponentClearance ComponentClearance_MountingHoles_FiducialMarks [InComponentClass('Mounting Holes') vs InComponentClass('FiducialMark')] p2: gap=30 collisioncheckmode=3 verticalgap=12 showdistances=FALSE
ComponentClearance ComponentClearance_Logo [InComponentClass('Logo')] p3: gap=10 collisioncheckmode=3 verticalgap=13 showdistances=FALSE
ComponentClearance ComponentClearance_ScrewToNut [(HasFootprint('NY PMS 440 0025 PH')) vs (HasFootprint('Keystone_1902C'))] p4: gap=5 collisioncheckmode=3 verticalgap=14 showdistances=FALSE
ComponentClearance ComponentClearance_MountingHoles [InComponentClass('Mounting Holes')] p5: gap=60 collisioncheckmode=3 verticalgap=100000 showdistances=FALSE
ComponentClearance ComponentClearance_SmallPassives [HasFootprint('0201*') or HasFootprint('0402*') or HasFootprint('0508') or HasFootprint('0603*') or HasFootprint('0612') or HasFootprint('0805*') or HasFootprint('0815*') or HasFootprint('0830*') or HasFootprint('1206*') or HasFootprint('1210*') or HasFootprint('1808*') or HasFootprint('1812*') or HasFootprint('1825*') or HasFootprint('2010*') or HasFootprint('2220*') or HasFootprint('2225*') or HasFootprint('2512*') or HasFootprint('2728*') or HasFootprint('3518*') vs HasFootprint('0201*') or HasFootprint('0402*') or HasFootprint('0508') or HasFootprint('0603*') or HasFootprint('0612') or HasFootprint('0805*') or HasFootprint('0815*') or HasFootprint('0830*') or HasFootprint('1206*') or HasFootprint('1210*') or HasFootprint('1808*') or HasFootprint('1812*') or HasFootprint('1825*') or HasFootprint('2010*') or HasFootprint('2220*') or HasFootprint('2225*') or HasFootprint('2512*') or HasFootprint('2728*') or HasFootprint('3518*')] p6: gap=15 collisioncheckmode=3 verticalgap=16 showdistances=FALSE
ComponentClearance ComponentClearance_THtoSMT [IsThruComponent vs IsSMTComponent] p7: gap=30 collisioncheckmode=3 verticalgap=17 showdistances=FALSE
ComponentClearance ComponentClearance_THtoTH [IsThruComponent vs IsThruComponent] p8: gap=50 collisioncheckmode=3 verticalgap=18 showdistances=FALSE
ComponentClearance [All] p9: gap=20 collisioncheckmode=3 verticalgap=19 showdistances=FALSE
DiffPairsRouting [All] p1: maxlimit=100 minlimit=10 mostfreqgap=10 toplayer_minwidth=15 toplayer_maxwidth=15 toplayer_prefwidth=15 midlayer1_minwidth=15 midlayer1_maxwidth=15 midlayer1_prefwidth=15 midlayer2_minwidth=15 midlayer2_maxwidth=15 midlayer2_prefwidth=15 midlayer3_minwidth=15 midlayer3_maxwidth=15 midlayer3_prefwidth=15 midlayer4_minwidth=15 midlayer4_maxwidth=15 midlayer4_prefwidth=15 midlayer5_minwidth=15 midlayer5_maxwidth=15 midlayer5_prefwidth=15 midlayer6_minwidth=15 midlayer6_maxwidth=15 midlayer6_prefwidth=15 midlayer7_minwidth=15 midlayer7_maxwidth=15 midlayer7_prefwidth=15 midlayer8_minwidth=15 midlayer8_maxwidth=15 midlayer8_prefwidth=15 bottomlayer_minwidth=15 bottomlayer_maxwidth=15 bottomlayer_prefwidth=15 maxuncoupledlength=1000
FabricationTestPointUsage TestPointUsage [All] p1: valid=2 allowmultiple=FALSE
FabricationTestpoint Testpoint [All] p1: side=3 testpointundercomponent=TRUE minsize=40 maxsize=100 preferedsize=60 minholesize=0 maxholesize=40 preferedholesize=32 testpointgrid=1 allowsidetop=TRUE allowsidebottom=TRUE usegrid=TRUE gridtolerance=0.01
FanoutControl Fanout_LCC [IsLCC] p1: bgadir=Out bgaviamode=Centered fanoutstyle=Auto fanoutdirection=Alternating viagrid=1 // Fanout_LCC (Default Rule)
FanoutControl Fanout_BGA [IsBGA] p2: bgadir=Out bgaviamode=Centered fanoutstyle=Auto fanoutdirection=Alternating viagrid=1 // Fanout_BGA (Default Rule)
FanoutControl Fanout_Default [All] p4: bgadir=Out bgaviamode=Centered fanoutstyle=Auto fanoutdirection=Alternating viagrid=1 // Fanout_Default (Default Rule)
FanoutControl Fanout_Small [(CompPinCount < 5)] p5: bgadir=Out bgaviamode=Centered fanoutstyle=Auto fanoutdirection=OutThenIn viagrid=1 // Fanout_Small (Default Rule)
HoleSize [All] p1: absolutevalues=TRUE maxlimit=251 minlimit=7.5 maxpercent=80.000 minpercent=20.000
MinimumAnnularRing MinimumAnnularRing_ThermalPadVias [IsVia and InAnyComponent] p1: minimumring=4.5
MinimumAnnularRing [All] p2: minimumring=4.9
MinimumSolderMaskSliver MinimumSolderMaskSliver_Logo [InComponentClass('Logo') vs InComponentClass('Logo')] p1: minsoldermaskwidth=0.7
MinimumSolderMaskSliver [All] p2 off: minsoldermaskwidth=3.94
PlaneClearance [All] p1: clearance=6.5
PlaneConnect [All] p1: planeconnectstyle=Relief reliefexpansion=10 reliefentries=4 reliefconductorwidth=10 reliefairgap=10
PolygonConnect PolygonConnect_NoTherm [InComponentClass('NoTherm') or InNetClass('NoTherm')] p1: connectstyle=Direct reliefconductorwidth=10 reliefentries=4 polygonreliefangle="90 Angle" airgapwidth=10
PolygonConnect PolygonConnect_Via [IsVia] p2: connectstyle=Direct reliefconductorwidth=10 reliefentries=4 polygonreliefangle="90 Angle" airgapwidth=10
PolygonConnect [All] p3: connectstyle=Relief reliefconductorwidth=10 reliefentries=4 polygonreliefangle="90 Angle" airgapwidth=6.2
RoutingVias ThermalPadVias [IsVia and InAnyComponent] p1: holewidth=10 width=20 viastyle="Through Hole" minholewidth=7.87 minwidth=19.68 maxholewidth=12.99 maxwidth=23.62
RoutingVias [All] p2: holewidth=10 width=20 viastyle="Through Hole" minholewidth=7.87 minwidth=16 maxholewidth=40 maxwidth=65
SMDToCorner [All] p1: distance=30000
SilkToSilkClearance SilkToSilkClearance_Pb-FreeLogo [(HasFootprint('Pb-Free_Overlay_Medium') OR HasFootprint('Pb-Free_Overlay_Small')) vs (HasFootprint('Pb-Free_Overlay_Medium') OR HasFootprint('Pb-Free_Overlay_Small'))] p1 off: silktosilkclearance=0
SilkToSilkClearance [All] p2 off: silktosilkclearance=5
SilkToSolderMaskClearance SilkscreenOverComponentPads [IsPad] p1: minsilkscreentomaskgap=5 clearancetoexposedcopper=TRUE
SolderMaskExpansion [All] p1: expansion=1.97
Width [All] p1 off: maxlimit=100 minlimit=6 preferedwidth=10 checkconnectedcopper=TRUE
15 further rules are at their usual default settings.

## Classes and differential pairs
component class Header: J3
net class PPRI: VPRI_SW
component class HV_NoErr: R5
net class NoTherm: SEC_D1 SEC_D2 SPGND VBUS_N VBUS_P VOUT VPRI_CAP VPRI_SW
component class NoTherm: Q1 R36 R39 R44 R47
component class SV601229B_Cover_Sheet: !PCB1 FID1 FID2 FID3 H1 H2 H3 H4 LBL1 LOGO1 Logo2 Logo3 LOGO4 Logo6 ZZ1
component class AssemblyNote: ZZ1
component class Label: LBL1
component class Logo: LOGO1 Logo2 LOGO4 Logo6
component class "Mounting Holes": H1 H2 H3 H4
net class HV_input: VBUS_N VBUS_P
component class XBP: C15 C16 C17 C18 C20 C21 C22 C23 C54 C55 C56 C57
component class SV601229B_Power_Stage: C3 C4 C12 C13 C14 C15 C16 C17 C18 C19 C20 C21 C22 C23 C26 C32 C33 C34 C36 C38 C39 C40 C41 C42 C43 C44 C45 C46 C47 C48 C49 C53 C54 C55 C56 C57 D3 D4 J1 J4 J5 J6 L1 L2 NT1 NT2 NT3 NT4 Q2 Q3 Q4 Q5 R7 R25 R26 R48 R49 R55 R67 R68 T1 TP3 TP4 TP5 TP6 TP7 TP8 TP9 TP10 TP11 TP12 TP13 TP14 U3 U7 U8
component class SV601229B_Controller: C1 C2 C5 C6 C7 C8 C9 C10 C11 C24 C25 C27 C28 C29 C30 C31 C35 C37 C50 C51 C52 D1 D2 D5 J2 J3 Q1 R1 R2 R3 R4 R5 R6 R8 R9 R10 R11 R12 R13 R14 R15 R16 R17 R18 R19 R20 R21 R22 R23 R24 R27 R28 R29 R30 R31 R32 R33 R34 R35 R36 R37 R38 R39 R40 R41 R42 R43 R44 R45 R46 R47 R50 R51 R52 R53 R54 R56 R57 R58 R59 R60 R61 R62 R63 R64 RT1 RT2 S1 TP1 TP2 TP15 TP16 U1 U2 U4 U5 U6
net class HV1: VBUS_P
net class HV2: VPRI_CAP VPRI_SW

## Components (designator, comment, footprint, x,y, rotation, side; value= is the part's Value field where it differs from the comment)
C1 "C0805C225K4RACTU" 0805 350,625 r270 top value=2.2uF
C2 "C1005X7R1H104K050BB" 0402 400,750 r90 top value=0.1uF
C3 "EMVA101ADA220MHA0G" CAPSMT_62_HA0 696,1632 r0 top value=22uF
C4 "EMVA101ADA220MHA0G" CAPSMT_62_HA0 696,1232 r0 top value=22uF
C5 "C1005X7R1C224K050BC" 0402 500,825 r0 top value=0.22uF
C6 "C0805C225K4RACTU" 0805 750,675 r270 top value=2.2uF
C7 "C0805C225K4RACTU" 0805 740,510 r270 top value=2.2uF
C8 "C1005X7R1C224K050BC" 0402 950,500 r180 top value=0.22uF
C9 "C0805C225K4RACTU" 0805 955,290 r0 top value=2.2uF
C10 "C0805C225K4RACTU" 0805 955,215 r0 top value=2.2uF
C11 "C1005X7R1C103K050BA" 0402 1090,375 r90 top value=0.01uF
C12 "GRM188R72A104KA35J" 0603S 1200,1500 r180 top value=0.1uF
C13 "GRM188R72A104KA35J" 0603S 1200,1445 r180 top value=0.1uF
C14 "GRM188R72A104KA35J" 0603S 1200,1390 r180 top value=0.1uF
C15 "GRM188R72A104KA35J" 0603S 1200,1335 r180 top value=0.1uF
C16 "GRM188R72A104KA35J" 0603S 1200,1280 r180 top value=0.1uF
C17 "GRM188R72A104KA35J" 0603S 1200,1225 r180 top value=0.1uF
C18 "GRM188R72A104KA35J" 0603S 1200,1170 r180 top value=0.1uF
C19 "C1005X7R1H104K050BB" 0402 1215,1070 r90 top value=0.1uF
C20 "C2012X5R1H475K125AB" 0805_HV 1400,1650 r0 top value=4.7uF
C21 "C2012X5R1H475K125AB" 0805_HV 1400,1570 r0 top value=4.7uF
C22 "C2012X5R1H475K125AB" 0805_HV 1400,1490 r0 top value=4.7uF
C23 "C2012X5R1H475K125AB" 0805_HV 1400,1410 r0 top value=4.7uF
C24 "GRM155R61A105KE15D" 0402 1400,760 r0 top value=1uF
C25 "GRM155R61A105KE15D" 0402 1550,895 r90 top value=1uF
C26 "GRM155R61A105KE15D" 0402 1540,1065 r90 top value=1uF
C27 "GRM1555C1H100JA01D" 0402 1660.52,868.1 r0 top value=10pF
C28 "GRM155R61A105KE15D" 0402 1630,535 r90 top value=1uF
C29 "GRM188R71C334KA01D" 0603 1740,740 r270 top value=0.33uF
C30 "GRM188R71C334KA01D" 0603 1740,620 r90 top value=0.33uF
C31 "C0603C224K4RACTU" 0603 2535,230 r270 top value=0.22uF
C32 "T520B157M006ATE025" 3528-21 2700,1685 r0 top value=150uF
C33 "T520B157M006ATE025" 3528-21 2695,1435 r0 top value=150uF
C34 "T520B157M006ATE025" 3528-21 2695,1295 r0 top value=150uF
C35 "C1005X7R1C103K050BA" 0402 2685,340 r0 top value=0.01uF
C36 "T520B157M006ATE025" 3528-21 2800,420 r270 top value=150uF
C37 "C0603C224K4RACTU" 0603 3325,120 r90 top value=0.22uF
C38 "GRM1555C1H100JA01D" 0402 2660,1605 r180 bottom value=10pF
C39 "C1005X7R1C224K050BC" 0402 2622.69,1401.98 r180 bottom value=0.22uF
C40 "GRM1555C1H100JA01D" 0402 2655,1280 r180 bottom value=10pF
C41 "C1005X7R1C224K050BC" 0402 2615,1075 r180 bottom value=0.22uF
C42 "GRM21BR61A476ME15" 0805L 2510,1655 r90 bottom value=47uF
C43 "GRM21BR61A476ME15" 0805L 2510,1430 r270 bottom value=47uF
C44 "GRM21BR61A476ME15" 0805L 2510,1315 r90 bottom value=47uF
C45 "GRM21BR61A476ME15" 0805L 2520,1090 r270 bottom value=47uF
C46 "GRM21BR61A476ME15" 0805L 2435,1655 r90 bottom value=47uF
C47 "GRM21BR61A476ME15" 0805L 2430,1430 r270 bottom value=47uF
C48 "GRM21BR61A476ME15" 0805L 2430,1315 r90 bottom value=47uF
C49 "GRM21BR61A476ME15" 0805L 2445,1090 r270 bottom value=47uF
C50 "GRM1555C1E681JA01D" 0402 1685,860 r0 bottom value=680pF
C51 "C1005X7R1C224K050BC" 0402 1613.11,803.62 r0 bottom value=0.22uF
C52 "GRM155R71C472KA01D" 0402 1590,535 r90 bottom value=4700pF
C53 "C1005X7R1H104K050BB" 0402 1540,1065 r90 bottom value=0.1uF
C54 "C2012X5R1H475K125AB" 0805_HV 1401.65,1647.01 r180 bottom value=4.7uF
C55 "C2012X5R1H475K125AB" 0805_HV 1401.65,1568.01 r180 bottom value=4.7uF
C56 "C2012X5R1H475K125AB" 0805_HV 1401.65,1488.01 r180 bottom value=4.7uF
C57 "C2012X5R1H475K125AB" 0805_HV 1401.65,1408.01 r180 bottom value=4.7uF
D1 "150060GS75000" WL-SMCW_GREEN 1820,300 r90 top value=Green
D2 "150060GS75000" WL-SMCW_GREEN 1900,300 r90 top value=Green
D3 "SDM10U45-7-F" SOD-523 2125,730 r180 top value=45V
D4 "SDM10U45-7-F" SOD-523 2125,675 r180 top value=45V
D5 "1SMA5927BT3G" SMA 2875,300 r270 bottom value=12V
H1 "NY PMS 440 0025 PH" "NY PMS 440 0025 PH" 200,2175 r0 top locked
H2 "NY PMS 440 0025 PH" "NY PMS 440 0025 PH" 200,200 r90 top
H3 "NY PMS 440 0025 PH" "NY PMS 440 0025 PH" 3675,2175 r0 top locked
H4 "NY PMS 440 0025 PH" "NY PMS 440 0025 PH" 3675,200 r0 top locked
J1 "1715721" PhoenixContact_1715721 225,1350 r270 top
J2 "282834-2" TEC_282834-2 150,700 r90 top
J3 "TSW-103-07-T-S" Samtec_TSW-103-07-T-S 1610,295 r180 top
J4 "142-0701-201" Johnson_142-0701-20x 3180,2130 r90 top
J5 "575-4" Keystone_575-4 3575,1625 r0 top locked
J6 "575-4" Keystone_575-4 3575,875 r0 top locked
L1 "744308025" WE-HCM_1070 2345,1545 r0 top value=250nH
L2 "744308025" WE-HCM_1070 2345,1203.74 r0 top value=250nH
LBL1 "Size: 0.65\" x 0.20 \"" Label_650x200 767,2162.63 r180 bottom
LOGO1 "DANGER HIGH VOLTAGE" IEC_HighVoltage_Small 225,1000 r0 top
Logo2 "Texas Instruments" TI_Stacked_Overlay_Small 815,2135 r0 top
Logo3 "FCC disclaimer" FCC_disclaimer 975,2335 r0 top
LOGO4 "CAUTION HOT SURFACE" IEC_HotSurface_Small 1685,1870 r0 top
Logo6 "Texas Instruments" TI_Symbol_Overlay_Small 720,1890 r180 bottom
NT1 "Net-tie connecting GND polygons under signal traces" NETTIE_midlayer2 2090,840 r90 top net-tie
NT2 "Net-tie connecting GND polygons under signal traces" NETTIE_midlayer2 2090,875 r90 top net-tie
NT3 "Net-tie connecting GND polygons under signal traces" Net-Tie_50milWide_30milLong 2315,960 r90 bottom net-tie
NT4 "Net-tie connecting GND polygons under signal traces" Net-Tie_50milWide_30milLong 1585,975 r270 bottom net-tie
Q1 "CSD16321Q5" TRANS_NexFET_Q5 3000,325 r90 top value=25V
Q2 "EPC2023ENGR" EPC2023 2250,1650 r75 bottom value=30V
Q3 "EPC2023ENGR" EPC2023 2250,1470 r105 bottom value=30V
Q4 "EPC2023ENGR" EPC2023 2250,1280 r75 bottom value=30V
Q5 "EPC2023ENGR" EPC2023 2250,1100 r105 bottom value=30V
R1 "ERJ-2BSFR10X" 0402 925,610 r270 top value=0.1
R2 "ERJ-2BSFR10X" 0402 1025,775 r0 top value=0.1
R3 "ERJ-2BSFR10X" 0402 1025,700 r0 top value=0.1
R4 "CRCW04022K74FKED" 0402 1050,525 r90 top value=2.74k
R5 "CRCW040247K0JNED" 0402 1210,905 r90 top value=47k
R6 "CRCW040247K0JNED" 0402 1210,805 r90 top value=47k
R7 "CRCW0603150KFKEA" 0603 1395,1715 r180 top value=150k
R8 "CRCW04022K74FKED" 0402 1400,845 r180 top value=2.74k
R9 "CRCW04022K74FKED" 0402 1400,800 r180 top value=2.74k
R10 "CRCW040210R0FKED" 0402 1400,680 r0 top value=10.0
R11 "CRCW040210R0FKED" 0402 1400,720 r0 top value=10.0
R12 "CRCW040210K0FKED" 0402 1430,535 r90 top value=10.0k
R13 "CRCW040210R0FKED" 0402 1510,895 r90 top value=10.0
R14 "CRCW0402100KFKED" 0402 1510,535 r90 top value=100k
R15 "CRCW040239K2FKED" 0402 1470,535 r270 top value=39.2k
R16 "CRCW04025K11FKED" 0402 1590.52,893.1 r270 top value=5.11k
R17 "CRCW0402178KFKED" 0402 1590,535 r90 top value=178k
R18 "CRCW040210K0FKED" 0402 1660.52,918.1 r180 top value=10.0k
R19 "CRCW040224K0JNED" 0402 1675,535 r270 top value=24k
R20 "CRCW040220K0FKED" 0402 1795,740 r90 top value=20.0k
R21 "CRCW040220K0FKED" 0402 1795,615 r270 top value=20.0k
R22 "CRCW040210K0FKED" 0402 2005,660 r180 top value=10.0k
R23 "CRCW040210K0FKED" 0402 1860,425 r90 top value=10.0k
R24 "CRCW0402470RJNED" 0402 1910,425 r90 top value=470
R25 "CRCW040210R0FKED" 0402 2125,780 r0 top value=10.0
R26 "CRCW040210R0FKED" 0402 2130,625 r0 top value=10.0
R27 "CRCW04022K74FKED" 0402 2215,1775 r180 top value=2.74k
R28 "CRCW04022K74FKED" 0402 2220,968.03 r180 top value=2.74k
R29 "CRCW04023K32FKED" 0402 2410,1775 r180 top value=3.32k
R30 "CRCW04023K32FKED" 0402 2420,968.03 r180 top value=3.32k
R31 "CRCW040239K2FKED" 0402 2515,485 r180 top value=39.2k
R32 "CRCW040239K2FKED" 0402 2590,340 r0 top value=39.2k
R33 "CRCW040239K2FKED" 0402 2633,384 r180 top value=39.2k
R34 "CRA2512-FZ-R040ELF" 2512 2875,1055 r180 top value=0.04
R35 "CRA2512-FZ-R040ELF" 2512 2875,845 r0 top value=0.04
R36 "CRA2512-FZ-R040ELF" 2512 2875,615 r180 top value=0.04
R37 "CRA2512-FZ-R040ELF" 2512 3180,1055 r180 top value=0.04
R38 "CRA2512-FZ-R040ELF" 2512 3180,845 r0 top value=0.04
R39 "CRA2512-FZ-R040ELF" 2512 3180,615 r180 top value=0.04
R40 "CRCW04021K00FKED" 0402 3205,240 r180 top value=1.00k
R41 "CRCW040210K0FKED" 0402 2005,705 r180 top value=10.0k
R42 "CRA2512-FZ-R040ELF" 2512 3180,1055 r180 bottom value=0.04
R43 "CRA2512-FZ-R040ELF" 2512 3180,845 r0 bottom value=0.04
R44 "CRA2512-FZ-R040ELF" 2512 3180,615 r180 bottom value=0.04
R45 "CRA2512-FZ-R040ELF" 2512 2875,1055 r180 bottom value=0.04
R46 "CRA2512-FZ-R040ELF" 2512 2875,845 r0 bottom value=0.04
R47 "CRA2512-FZ-R040ELF" 2512 2875,615 r180 bottom value=0.04
R48 "CRCW06032R20JNEA" 0603 2435,1540 r180 bottom value=2.2
R49 "CRCW06032R20JNEA" 0603 2460,1200 r0 bottom value=2.2
R50 "CRCW040210K0FKED" 0402 1715,535 r270 bottom value=10.0k
R51 "CRCW040224K0JNED" 0402 1675,535 r270 bottom value=24k
R52 "CRCW040210K0FKED" 0402 1580,870 r180 bottom value=10.0k
R53 "CRCW040224K0JNED" 0402 1550,535 r270 bottom value=24k
R54 "CRCW0402100KFKED" 0402 1510,535 r270 bottom value=100k
R55 "CRCW0603150KFKEA" 0603 1395,1715 r0 bottom value=150k
R56 "CRCW040239K2FKED" 0402 1470,535 r270 bottom value=39.2k
R57 "CRCW0603150KFKEA" 0603 1420,525 r90 bottom value=150k
R58 "CRCW040210R0FKED" 0402 1760,820 r0 top value=10.0
R59 "CRCW040210R0FKED" 0402 1760,860 r0 top value=10.0
R60 "CRCW040210K0FKED" 0402 1810,425 r90 top value=10.0k
R61 "CRCW04021K00FKED" 0402 1768.04,736.65 r180 bottom value=1.00k
R62 "CRCW04021K00FKED" 0402 1768.04,776.65 r0 bottom value=1.00k
R63 "CRCW04021K00FKED" 0402 1775,860 r180 bottom value=1.00k
R64 "CRCW04021K00FKED" 0402 1770,820 r0 bottom value=1.00k
R67 "CRCW040210R0FKED" 0402 2455,930 r180 bottom value=10.0
R68 "CRCW040210R0FKED" 0402 2303.31,638.63 r90 top value=10.0
RT1 "NCP15XH103J03RC" 0402 2315,1775 r180 top value="10k ohm"
RT2 "NCP15XH103J03RC" 0402 2320,968.03 r180 top value="10k ohm"
S1 "204-212ST" SW_204-212 2200,325 r0 top
T1 "ER18-3.2-10-3F45-S" ER18_3to1_A 1820,1375 r0 top net-tie
TP1 "5011" Keystone5011 675,300 r90 top value=Black
TP2 "5010" Keystone5010 875,750 r90 top value=Red
TP3 "5010" Keystone5010 1000,1700 r0 top value=Red
TP4 "5011" Keystone5011 1000,1125 r0 top value=Black
TP5 "TESTPOINT_PIGTAIL" TP_PIGTAIL 1375,2035 r180 top
TP6 "TESTPOINT_PIGTAIL" TP_PIGTAIL 1595,2035 r180 top
TP7 "TESTPOINT_PIGTAIL" TP_PIGTAIL 1815,2035 r180 top
TP8 "TESTPOINT_PIGTAIL" TP_PIGTAIL 2035,2035 r180 top
TP9 "TESTPOINT_PIGTAIL" TP_PIGTAIL 2255,2035 r180 top
TP10 "TESTPOINT_PIGTAIL" TP_PIGTAIL 2475,2035 r180 top
TP11 "TESTPOINT_PIGTAIL" TP_PIGTAIL 2695,2035 r180 top
TP12 "5011" Keystone5011 2805,1835 r90 top value=Black
TP13 "TESTPOINT_PIGTAIL" TP_PIGTAIL 2915,2035 r180 top
TP14 "5010" Keystone5010 3055,1835 r0 top value=Red
TP15 "TP_PIGTAIL" TP_PIGTAIL 3195,390 r90 top
TP16 "TP_PIGTAIL" TP_PIGTAIL 1265,425 r0 top
U1 "LP38693MP-5.0/NOPB" MP05A_N 550,625 r270 top
U2 "LP2992AILD-3.3/NOPB" LDE06A 975,400 r180 top
U3 "LMG5200MOFR" MOF0009A 1378.35,1173.88 r0 top
U4 "TPS53632GRSM" RSM0032B_NV 1573.74,724.88 r0 top
U5 "LMC555CMM/NOPB" MUA08A_N 2640,190 r90 top
U6 "UCC27512DRSR" DRS0006A 3215,125 r90 top
U7 "UCC27512DRSR" DRS0006A 2640,1505 r90 bottom
U8 "UCC27512DRSR" DRS0006A 2635,1175 r90 bottom
ZZ1 "This Assembly Note is for PCB labels only" AssemblyNoteLabel -15,7838 r0 top

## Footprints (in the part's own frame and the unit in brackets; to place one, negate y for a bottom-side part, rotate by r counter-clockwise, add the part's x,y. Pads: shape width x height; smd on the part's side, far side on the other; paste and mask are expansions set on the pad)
0402 [mm] "0402 from SM-752 data"
  rect 0.8x0.6 smd: 1(-0.6,0) 2(0.6,0)
  silkscreen extent -1.22,-0.52 1.22,0.52, body extent -0.55,-0.3 0.55,0.3, height 0.6
0603 [mm] "0603 from SM-752 data"
  rect 1x0.95 smd: 1(-0.8,0) 2(0.8,0)
  silkscreen extent -1.52,-0.69 1.52,0.69, body extent -0.87,-0.47 0.87,0.47, height 1
0603S [mil]
  rect 20x35 smd: 1(-30,0) 2(30,0)
  silkscreen extent -10,-17 10,17, body extent -34,-19 34,19, height 39
0805 [mm] "0805 from SM-752 data"
  rect 1.3x1.5 smd: 1(-0.85,0) 2(0.85,0)
  silkscreen extent -1.72,-0.97 1.72,0.97, body extent -1.1,-0.72 1.1,0.72, height 1.45
0805_HV [mil] "0805 with 30mil clearance between pads"
  rect 50x63 smd: 1(-40,0) 2(40,0)
  silkscreen extent -74,-40 74,40, body extent -43,-29 43,29, height 57
0805L [mm] "0805 from SM-752 data"
  rect 1.1x1.4 smd: 1(-0.75,0) 2(0.75,0)
  body extent -1.1,-0.72 1.1,0.72, height 1.45
2512 [mm] "Chip Resistor, Body 6.3x3.2mm, IPC Medium Density"
  rect 1.3x3.4 smd: 1(-2.95,0) 2(2.95,0)
  silkscreen extent -1.9,-1.6 1.9,1.6, body extent -3.22,-1.67 3.22,1.67, height 0.71
3528-21 [mm] "Medium Density IPC, based on SM-782 section 8.4"
  rect 1.95x2.25 smd: 1(-1.375,0) 2(1.375,0)
  silkscreen extent -2.29,-1.5 0.76,1.5, body extent -1.85,-1.5 1.85,1.5, height 2.1
AssemblyNoteLabel [mil] "Assembly Note for PCB Labels"
CAPSMT_62_HA0 [mm] "8 x 10mm:  Chemi-Con HA0"
  rect 4.2x2.2 smd: 1(-3.65,0) 2(3.65,0)
  silkscreen extent -4.25,-4.25 4.25,4.25, body extent -4.25,-4.25 4.25,4.25, height 10.5
DRS0006A [mm] "SON, 6-Leads, Body 3x3mm, Pitch 0.95mm, Thermal Pad 2x1.3mm, TI Recommended"
  oval 0.7x0.35 smd: 1(-1.35,0.95) 2(-1.35,0) 3(-1.35,-0.95) 4(1.35,-0.95) 5(1.35,0) 6(1.35,0.95)
  rect 1.2x1.9 smd paste-0.6: 7(0,0)
  silkscreen extent -1.73,-1.73 1.73,1.73, body extent -1.57,-1.57 1.58,1.58, height 0.81
EPC2023 [mm] "SMD, 30-Leads, Body 6.05x2.3mm, Pitch 0.4mm"
  oval 0.7x0.18 smd paste-0.7 mask-0.01: 1(0.665,2.8) 2(-0.665,2.8) 3(0.665,2.4) 4(-0.665,2.4) 5(0.665,2) 6(-0.665,2) 7(0.665,1.6) 8(-0.665,1.6) 9(0.665,1.2) 10(-0.665,1.2) 11(0.665,0.8) 12(-0.665,0.8) 13(0.665,0.4) 14(-0.665,0.4) 15(0.665,0) 16(-0.665,0) 17(0.665,-0.4) 18(-0.665,-0.4) 19(0.665,-0.8) 20(-0.665,-0.8) 21(0.665,-1.2) 22(-0.665,-1.2) 23(0.665,-1.6) 24(-0.665,-1.6) 25(0.665,-2) 26(-0.665,-2) 27(0.665,-2.4) 28(-0.665,-2.4) 29(0.665,-2.8) 30(-0.665,-2.8)
  rrect67% 0.7x0.18 on Bottom Paste paste-0.7 mask+0.01: ""(-0.665,0.4) ""(-0.665,0) ""(-0.665,-0.8) ""(-0.665,-1.6) ""(-0.665,-0.4) ""(-0.665,-1.2) ""(-0.665,2.8) ""(-0.665,-2) ""(-0.665,2) ""(-0.665,-2.8) ""(-0.665,2.4) ""(-0.665,-2.4) ""(-0.665,1.6) ""(-0.665,0.8) ""(-0.665,1.2) ""(0.665,0.4) ""(0.665,0) ""(0.665,-0.8) ""(0.665,-1.6) ""(0.665,-0.4) ""(0.665,-1.2) ""(0.665,2.8) ""(0.665,-2) ""(0.665,2) ""(0.665,2.4) ""(0.665,-2.4) ""(0.665,1.6) ""(0.665,0.8) ""(0.665,-2.8) ""(0.665,1.2)
  silkscreen extent -1.28,-3.15 1.28,3.15, body extent -1.16,-3.04 1.16,3.04, height 0.79
ER18_3to1_A [mil]
  rect 20x100 on Mid8: 1(-266,197) 2(-286,197)
  rect 20x220 on Mid2 paste-1000: 3(199,-128.26) 4(219,-128.26) 11(199,-128.26) 12(219,-128.26)
  rect 20x220 on Mid1 paste-1000: 3(199,-128.26) 4(219,-128.26) 11(199,-128.26) 12(219,-128.26)
  rect 20x220 smd far side: 5(199,-128) 6(219,-128)
  rect 20x220 on Mid3: 5(199,-128) 6(219,-128)
  rect 20x220 on Mid5: 5(199,-128) 6(219,-128)
  rect 20x220 on Mid7: 5(199,-128) 6(219,-128)
  rect 20x220 on Mid6: 7(199,-128) 8(219,-128) 9(199,-128) 10(219,-128)
  Top Layer keep-out lines w2: -272,107 cw(c-151.29,107) -236.64,192.36 -207.14,221.86 ; -271,107 cw(c-150.29,107) -235.64,192.36 -206.14,221.86 ; -270.36,-104.64 ccw(c-149.64,-104.64) -235,-190 ; -269.36,-104.64 ccw(c-148.64,-104.64) -234,-190 ; -255.99,-163.25 ccw(c-152.5,-103.5) -237,-188 -207,-218 ; -254.99,-163.25 ccw(c-151.5,-103.5) -236,-188 -206,-218 ; -207.2,221.93 cw(c-7,2) 193.06,222.06 ; -207.06,-218.06 ccw(c-7,2) 141.4,-255.74 ; -206.2,221.93 cw(c-6,2) 194.06,222.06 ; -206.06,-218.06 ccw(c-6,2) 142.4,-255.74 ; -155.4,-255.74 ccw(c-7,2) 193.06,-218.06 ; -154.4,-255.74 ccw(c-6,2) 194.06,-218.06 ; 193,222 222.64,192.36 cw(c137.29,107) 258,107 258,-103 cw(c137.29,-103) 222.64,-188.36 193.14,-217.86 ; 194,222 223.64,192.36 cw(c138.29,107) 259,107 259,-103 cw(c138.29,-103) 223.64,-188.36 194.14,-217.86
  MidLayer1 region: 204,-18.26 204,-238.26 214,-238.26 214,-18.26
  MidLayer1 region: 204,-18.26 204,-238.26 214,-238.26 214,-18.26
  MidLayer1 keep-out lines w2: -206.14,221.6 -235.64,192.09 ccw(c-150.29,106.74) -271,106.74 -271,-103.26 ccw(c-150.29,-103.26) -235.64,-188.62 -206,-218.26 ; -206.06,-218.32 ccw(c-6,1.74) 142.4,-256 ; -206.06,221.8 cw(c-6,1.74) 142.4,259.47
  MidLayer2 region: 204,-18.26 204,-238.26 214,-238.26 214,-18.26
  MidLayer2 region: 204,-18.26 204,-238.26 214,-238.26 214,-18.26
  MidLayer2 keep-out lines w2: -206.14,221.6 -235.64,192.09 ccw(c-150.29,106.74) -271,106.74 -271,-103.26 ccw(c-150.29,-103.26) -235.64,-188.62 -206,-218.26 ; -206.06,-218.32 ccw(c-6,1.74) 142.4,-256 ; -206.06,221.8 cw(c-6,1.74) 142.4,259.47
  MidLayer3 region: 204,-18 204,-238 214,-238 214,-18
  MidLayer3 keep-out lines w2: -206.14,221.86 -235.64,192.36 ccw(c-150.29,107) -271,107 -271,-103 ccw(c-150.29,-103) -235.64,-188.36 -206,-218 ; -206.06,-218.06 ccw(c-6,2) 142.4,-255.74 ; -206.06,222.06 cw(c-6,2) 142.4,259.74
  MidLayer4 keep-out lines w2: -263.72,148.29 cw(c-150.29,107) -235.64,192.36 -206.14,221.86 ; -254.99,-163.25 ccw(c-151.5,-103.5) -236,-188 -206,-218 ; -206.06,-218.06 ccw(c-6,2) 142.4,-255.74 ; -206.06,222.06 cw(c-6,2) 142.4,259.74 ; -154.4,-255.74 ccw(c-6,2) 194.06,-218.06 ; -154.4,259.74 cw(c-6,2) 194.06,222.06 ; 194,222 223.64,192.36 cw(c138.29,107) 259,107 259,-103 cw(c138.29,-103) 223.64,-188.36 194.14,-217.86
  MidLayer5 region: 204,-18 204,-238 214,-238 214,-18
  MidLayer5 keep-out lines w2: -206.14,221.86 -235.64,192.36 ccw(c-150.29,107) -271,107 -271,-103 ccw(c-150.29,-103) -235.64,-188.36 -206,-218 ; -206.06,-218.06 ccw(c-6,2) 142.4,-255.74 ; -206.06,222.06 cw(c-6,2) 142.4,259.74
  MidLayer6 region: 204,-18 204,-238 214,-238 214,-18
  MidLayer6 region: 204,-18 204,-238 214,-238 214,-18
  MidLayer6 keep-out lines w2: -206.14,221.86 -235.64,192.36 ccw(c-150.29,107) -271,107 -271,-103 ccw(c-150.29,-103) -235.64,-188.36 -206,-218 ; -206.06,-218.06 ccw(c-6,2) 142.4,-255.74 ; -206.06,222.06 cw(c-6,2) 142.4,259.74
  MidLayer7 region: 204,-18 204,-238 214,-238 214,-18
  MidLayer7 keep-out lines w2: -206.14,221.86 -235.64,192.36 ccw(c-150.29,107) -271,107 -271,-103 ccw(c-150.29,-103) -235.64,-188.36 -206,-218 ; -206.06,-218.06 ccw(c-6,2) 142.4,-255.74 ; -206.06,222.06 cw(c-6,2) 142.4,259.74
  MidLayer8 region: -281,247 -281,147 -271,147 -271,247
  MidLayer8 keep-out lines w2: -271,-43 -271,-103 ccw(c-150.29,-103) -235.64,-188.36 -206,-218 ; -206.06,-218.06 ccw(c-6,2) 194.06,-218.06 ; -154.4,259.74 cw(c-6,2) 194.06,222.06 ; 194,222 223.64,192.36 cw(c138.29,107) 259,107 259,-103 cw(c138.29,-103) 223.64,-188.36 194.14,-217.86
  Bottom Layer region: 204,-18 204,-238 214,-238 214,-18
  Bottom Layer keep-out lines w2: -206.14,221.86 -235.64,192.36 ccw(c-150.29,107) -271,107 -271,-103 ccw(c-150.29,-103) -235.64,-188.36 -206,-218 ; -206.06,-218.06 ccw(c-6,2) 142.4,-255.74 ; -206.06,222.06 cw(c-6,2) 142.4,259.74
  Keep-Out Layer circle w8: c-1,2 r129.92
  Keep-Out Layer lines w6: -150.61,261.84 -178.17,261.84 cw(c-178.17,281.53) -197.85,281.53 -197.85,346.49 cw(c-178.17,346.49) -178.17,366.17 176.17,366.17 cw(c176.17,346.49) 195.85,346.49 195.85,281.53 cw(c176.17,281.53) 176.17,261.84 144.67,261.84 ; -146.67,-257.84 -178.17,-257.84 ccw(c-178.17,-277.53) -197.85,-277.53 -197.85,-342.49 ccw(c-178.17,-342.49) -178.17,-362.17 176.17,-362.17 ccw(c176.17,-342.49) 195.85,-342.49 195.85,-277.53 ccw(c176.17,-277.53) 176.17,-257.84 148.61,-257.84
  Keep-Out Layer lines w8: -150.3,-257.3 ccw(c-1,2) 148.3,-257.3 ; -150.3,261.3 cw(c-1,2) 148.3,261.3
  body extent -198,-362 196,366, height 63
FCC_disclaimer [mil]
IEC_HighVoltage_Small [mil]
  silkscreen extent -107,-88 107,97
IEC_HotSurface_Small [mil]
  silkscreen extent -107,-93 107,92
Johnson_142-0701-20x [mil] "Johnson Components recommended land pattern"
  round 95 hole 62: 1(0,0)
  round 100 hole 67: 2(100,100) 3(100,-100) 4(-100,-100) 5(-100,100)
  body extent -156,-156 156,156, height 375
Keystone5010 [mil] "Keystone Multipurpose loops"
  round 87 hole 63: 1(0,0)
  silkscreen extent -70,-70 70,70, body extent -63,-63 63,62, height 319
Keystone5011 [mil] "Keystone Multipurpose loops"
  round 87 hole 63: 1(0,0)
  silkscreen extent -70,-70 70,70, body extent -63,-63 63,62, height 319
Keystone_575-4 [mm] "Banana Jack"
  round 10 hole 5.45: 1(0,0)
  body extent -3.95,-3.95 3.92,3.93, height 2.36
Label_650x200 [mil] "Thermal Transfer Label"
  round 1 on Mech14: 0(0,0)
  silkscreen extent -325,-100 325,100, body extent -325,-100 325,100, height 1
LDE06A [mm] "PSON, 6-Leads, Body 2.92x3.29 mm, Pitch 0.95mm, NSC Recommended"
  rect 0.5x0.35 smd paste-0.175 mask+0.051: 1(-1.295,0.95) 2(-1.295,0) 3(-1.295,-0.95) 4(1.295,-0.95) 5(1.295,0) 6(1.295,0.95)
  rect 1.2x1.92 smd paste-0.6 mask+0.051: 7(0,0)
  silkscreen extent -2.52,-1.66 1.85,1.67, body extent -1.69,-1.51 1.69,1.51, height 0.8
MOF0009A [mm]
  rrect25% 0.8x4.35 smd paste-1.5 mask-0.05: 1(-2.55,1.78) 8(2.55,1.78)
  rrect50% 0.7x0.59 on Top Paste: 1A(-2.55,3.56) 1B(-2.55,2.67) 1C(-2.55,1.78) 1D(-2.55,0.89) 1E(-2.55,0) 8A(2.55,3.56) 8B(2.55,2.67) 8C(2.55,1.78) 8D(2.55,0.89) 8E(2.55,0)
  rrect33% 0.8x0.6 smd mask-0.05: 2(-2.55,-2.05) 3(-2.55,-3.25) 6(2.55,-3.25) 7(2.55,-2.05)
  rrect33% 0.6x0.8 smd mask-0.05: 4(-0.9,-3.55) 5(0.9,-3.55)
  rrect17% 1.15x4.35 smd paste-1.5 mask-0.05: 9(0,1.78)
  rrect50% 1.05x0.59 on Top Paste: 9A(0,3.56) 9B(0,2.67) 9C(0,1.78) 9D(0,0.89) 9E(0,0)
  silkscreen extent -3.2,-4.2 3.2,4.2, body extent -3,-4 3,4, height 1.92
MP05A_N [mm] "SOT223, 5-Leads, Body 6.5x3.5mm, Pitch 1.5mm, Lead Span 7mm, IPC Medium Density"
  rect 2.4x1 smd: 1(-2.9,2.25) 2(-2.9,0.75) 3(-2.9,-0.75) 4(-2.9,-2.25)
  rect 2.4x3.2 smd: 5(2.9,0)
  silkscreen extent -3.02,-3.35 1.4,3.43, body extent -1.85,-3.35 1.85,3.35, height 1.8
MUA08A_N [mm] "TSOP, 8-Leads, Body 3x3mm, Pitch 0.65mm, IPC Medium Density"
  oval 1.7x0.45 smd: 1(-2.1,0.975) 2(-2.1,0.325) 3(-2.1,-0.325) 4(-2.1,-0.975) 5(2.1,-0.975) 6(2.1,-0.325) 7(2.1,0.325) 8(2.1,0.975)
  silkscreen extent -2.22,-1.55 0.85,1.87, body extent -1.6,-1.6 1.6,1.6, height 1.09
Net-Tie_50milWide_30milLong [mil] "50mil net tie, no solder mask opening, no solder paste"
  rect 30x50 smd paste-20 mask-20: 1(-15,0) 2(15,0)
NETTIE_midlayer2 [mil] "Net Tie"
  rect 10x21 on Mid2: 1(0,10) 2(0,-10)
"NY PMS 440 0025 PH" [mm] "4-40 nylon screw and mounting hole"
  round 8 hole 3.2: 1(0,0)
  body extent -3.3,-3.3 3.3,3.3, height 2.69
PhoenixContact_1715721 [mm] "Phoenix Contact 1715721 used on LM3445 design from Longmont"
  rrect5% 1.905x1.905 hole 1.3: 1(-2.54,0)
  round 1.9 hole 1.3: 2(2.54,0)
  silkscreen extent -5.82,-5.25 5.08,5.2, body extent -5.82,-4.6 5.08,5.2, height 14.2
RSM0032B_NV [mm] "QFN, 32-Leads, Body 4x4mm, Pitch 0.4mm, Thermal Pad 2.8x2.8mm, TI Recommended"
  oval 0.6x0.2 smd: 1(-1.9,1.4) 2(-1.9,1) 3(-1.9,0.6) 4(-1.9,0.2) 5(-1.9,-0.2) 6(-1.9,-0.6) 7(-1.9,-1) 8(-1.9,-1.4) 17(1.9,-1.4) 18(1.9,-1) 19(1.9,-0.6) 20(1.9,-0.2) 21(1.9,0.2) 22(1.9,0.6) 23(1.9,1) 24(1.9,1.4)
  oval 0.2x0.6 smd: 9(-1.4,-1.9) 10(-1,-1.9) 11(-0.6,-1.9) 12(-0.2,-1.9) 13(0.2,-1.9) 14(0.6,-1.9) 15(1,-1.9) 16(1.4,-1.9) 25(1.4,1.9) 26(1,1.9) 27(0.6,1.9) 28(0.2,1.9) 29(-0.2,1.9) 30(-0.6,1.9) 31(-1,1.9) 32(-1.4,1.9)
  rect 2.8x2.8 smd paste-1.4: 33(0,0)
  silkscreen extent -2.23,-2.23 2.23,2.23, body extent -2.07,-2.07 2.08,2.08, height 1.01
Samtec_TSW-103-07-T-S [mm] "Header, 2.54 mm, 3x1, TH"
  rect 1.55x1.55 hole 1.02: 1(-2.54,0)
  round 1.55 hole 1.02: 2(0,0) 3(2.54,0)
  silkscreen extent -3.81,-1.75 3.81,1.27, body extent -3.81,-1.27 3.81,1.27, height 8.39
SMA [mm] "Molded Diode, 2-Leads, Body 4.3x2.6mm, IPC Medium Density, based on OnSemi component dimensions and land pattern"
  rect 2x2 smd: 1(-2,0) 2(2,0)
  silkscreen extent -3.66,-1.57 2.79,1.57, body extent -2.6,-1.3 2.6,1.3, height 2.42
SOD-523 [mm] "NXP Semiconductor recommended land pattern, nominal STEP model"
  rect 0.8x0.6 smd paste-0.05: 1(-0.55,0) 2(0.55,0)
  silkscreen extent -1.6,-0.64 1.2,0.63, body extent -0.8,-0.4 0.8,0.4, height 0.72
SW_204-212 [mil] "DPST, 8-Leads, 2 Pos, Body 12.34x9.78mm, Pitch 2.54 mm, SMD"
  rect 44x96 smd: 1(-150,169.5) 2(-150,-169.5) 3(-50,169.5) 4(-50,-169.5) 5(50,169.5) 6(50,-169.5) 7(150,169.5) 8(150,-169.5)
  silkscreen extent -260,-198 248,198, body extent -248,-201 248,201, height 323
TEC_282834-2 [mm] "TEC"
  rect 1.6x1.6 hole 1.1: 1(-1.27,0)
  round 1.6 hole 1.1: 2(1.27,0)
  silkscreen extent -3.66,-3.4 2.9,3.4, body extent -2.77,-3.25 2.77,3.25, height 10.01
TI_Stacked_Overlay_Small [mil]
  silkscreen extent -418,-98 418,98
TI_Symbol_Overlay_Small [mil]
  silkscreen extent -90,-88 91,88
TP_PIGTAIL [mil] "Scope pigtail footprint"
  round 60 hole 42: 1(0,0)
  round 46 hole 32: 2(0,-200)
  silkscreen extent -50,-230 50,50
TRANS_NexFET_Q5 [mm] "TI recommended land pattern (nominal) M0139-01"
  rect 0.75x0.675 smd mask+0.051: 1(-2.776,1.917) 2(-2.776,0.639) 3(-2.776,-0.639) 4(-2.776,-1.917)
  rect 0.655x0.675 smd mask+0.051: 5(2.776,-1.917) 6(2.776,-0.639) 7(2.776,0.639) 8(2.776,1.917)
  rect 4.295x4.51 smd paste-2.2 mask+0.051: 9(0.301,0)
  silkscreen extent -3.4,-2.8 3.4,2.8, body extent -3.05,-2.55 3.05,2.55, height 1.06
WE-HCM_1070 [mm] "WURTH ELEKTRONIK"
  rect 3.6x2.6 smd: 1(-3.8,0) 2(3.8,0)
  silkscreen extent -5.4,-3.7 5.4,3.7, body extent -5.3,-3.7 5.3,3.7, height 7
WL-SMCW_GREEN [mm] "WURTH"
  rect 0.8x0.8 smd: 1(-0.8,0) 2(0.8,0)
  silkscreen extent -1.9,-0.8 1.2,0.8, body extent -0.85,-0.45 0.85,0.45, height 0.8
